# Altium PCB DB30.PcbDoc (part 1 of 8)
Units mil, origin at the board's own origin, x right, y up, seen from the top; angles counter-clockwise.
Board outline 3236.22 x 4456.69 mil, 8 copper layers (Top Layer, MidLayer1, MidLayer2, GND-Layer5, MidLayer3, VCC, MidLayer4, Bottom Layer), stack 61.8 mil thick; 219 components, 472 nets, 1811 pads, 1561 vias.
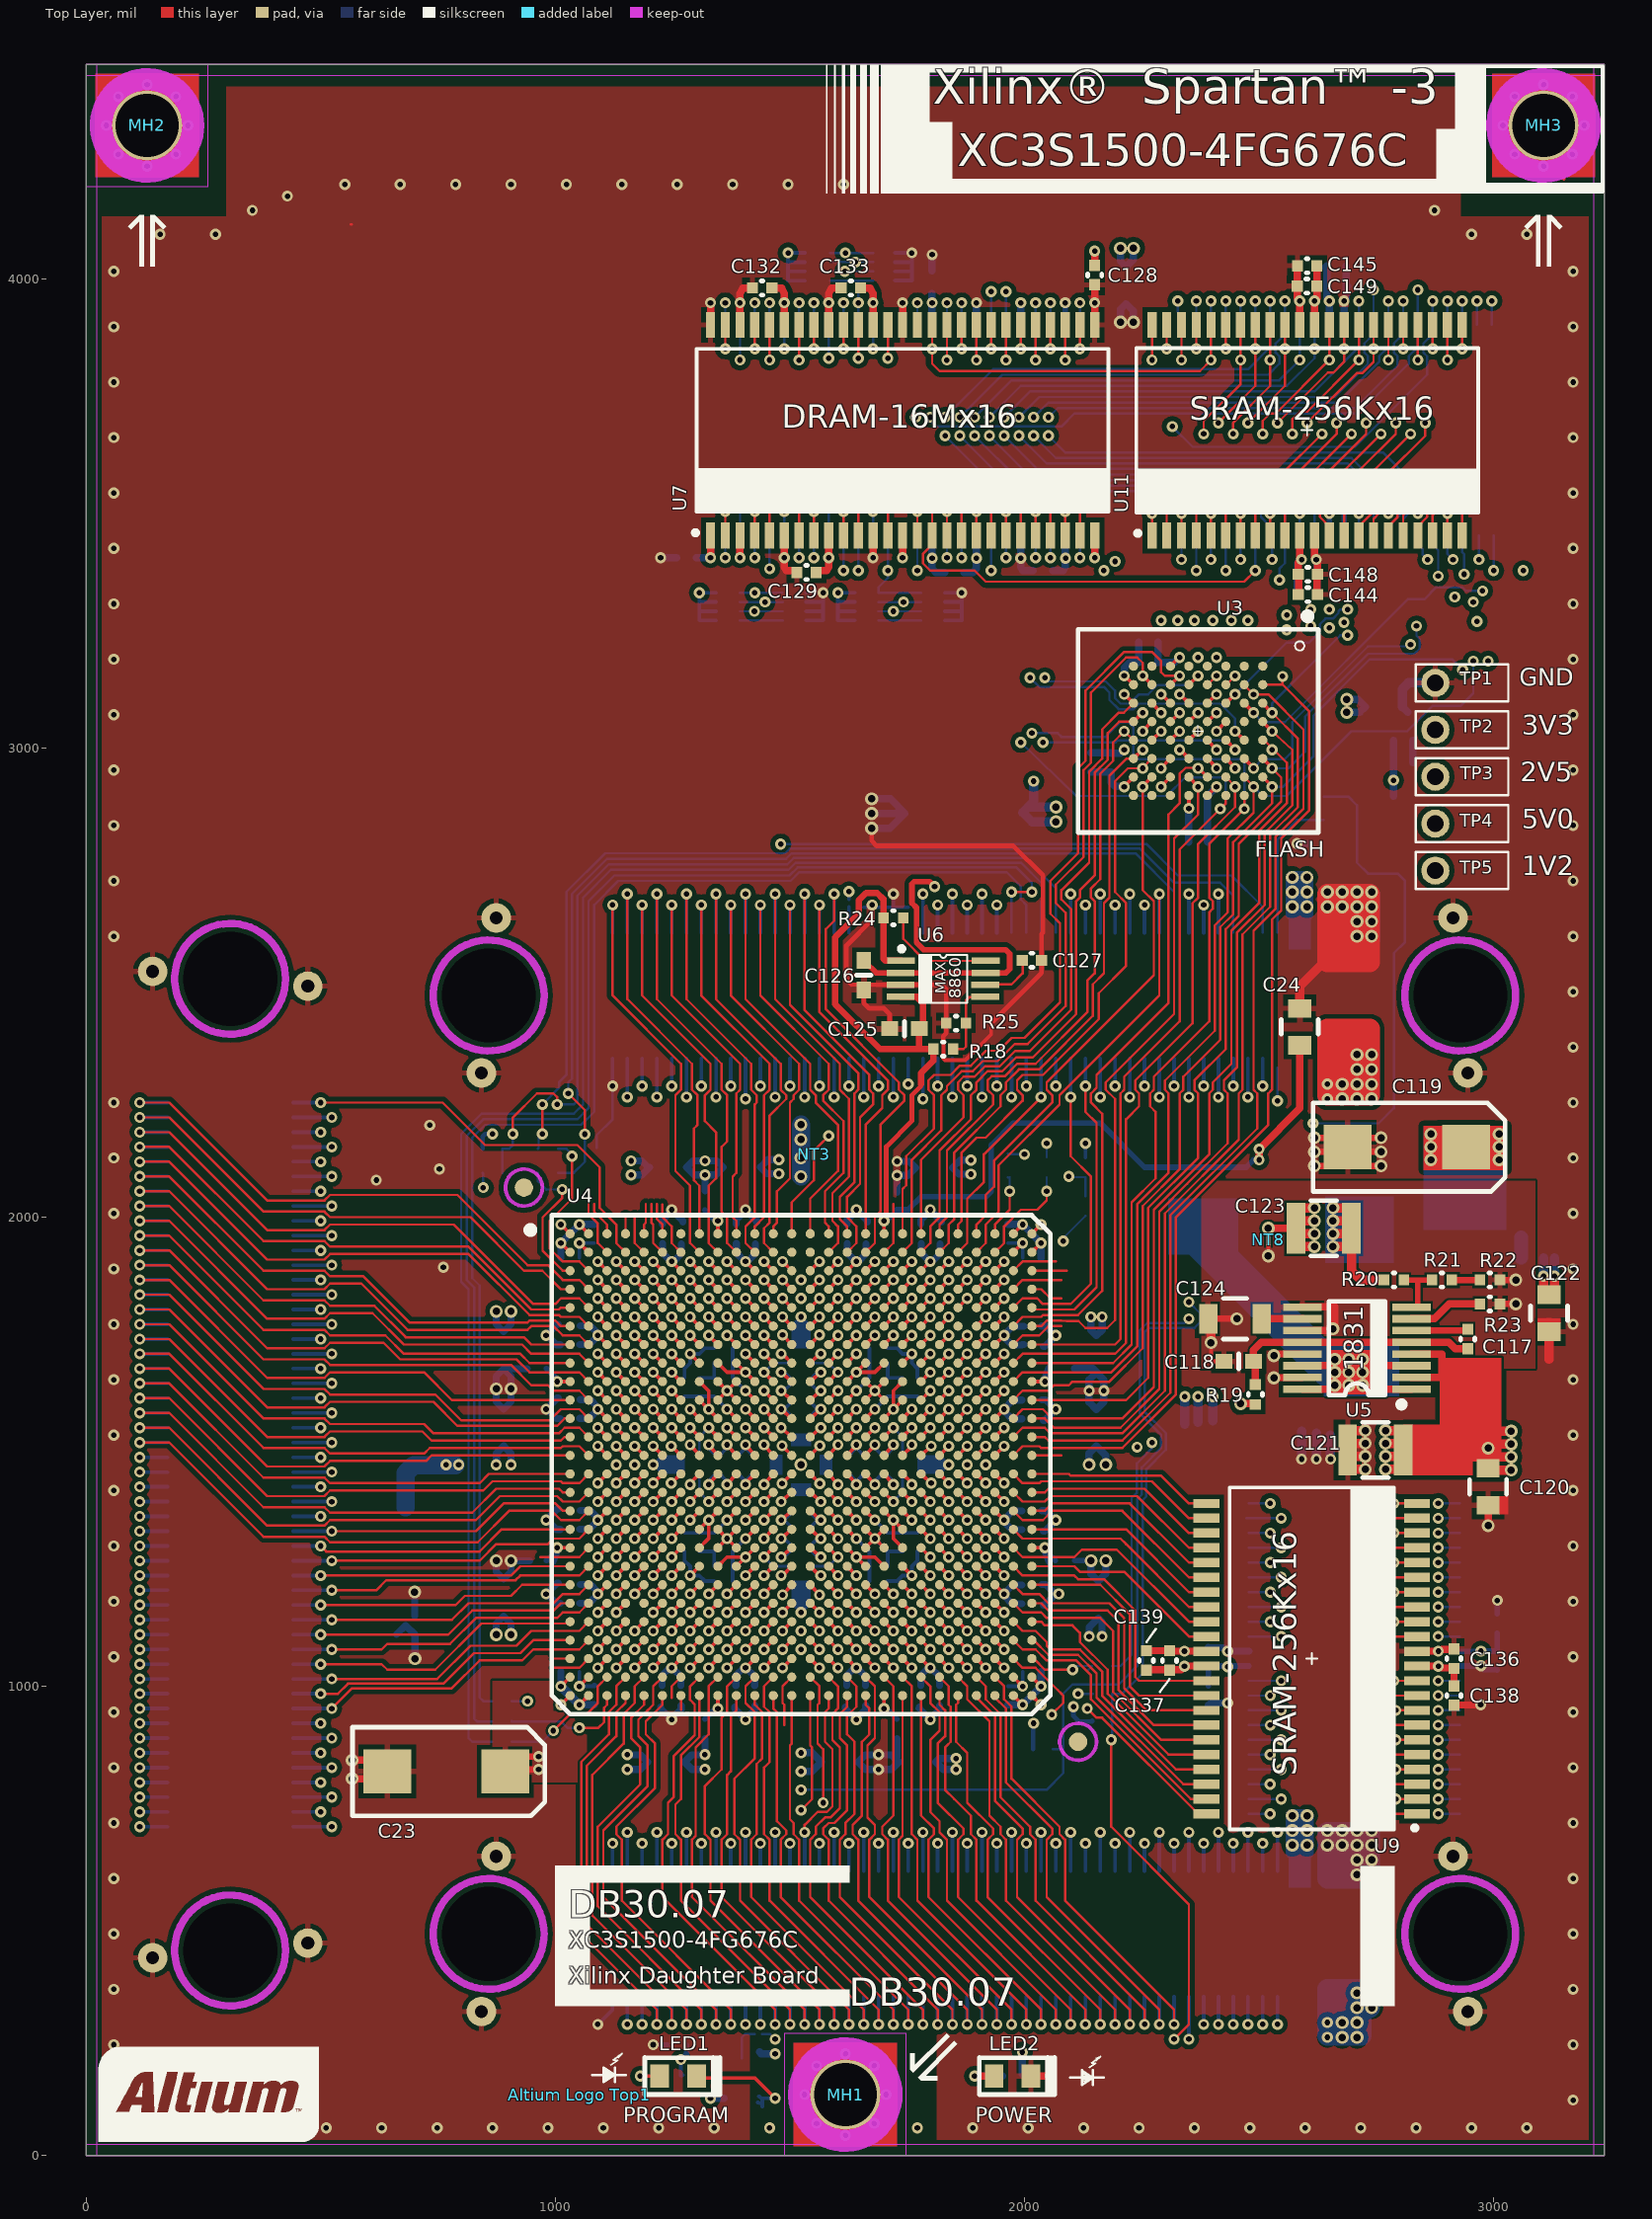
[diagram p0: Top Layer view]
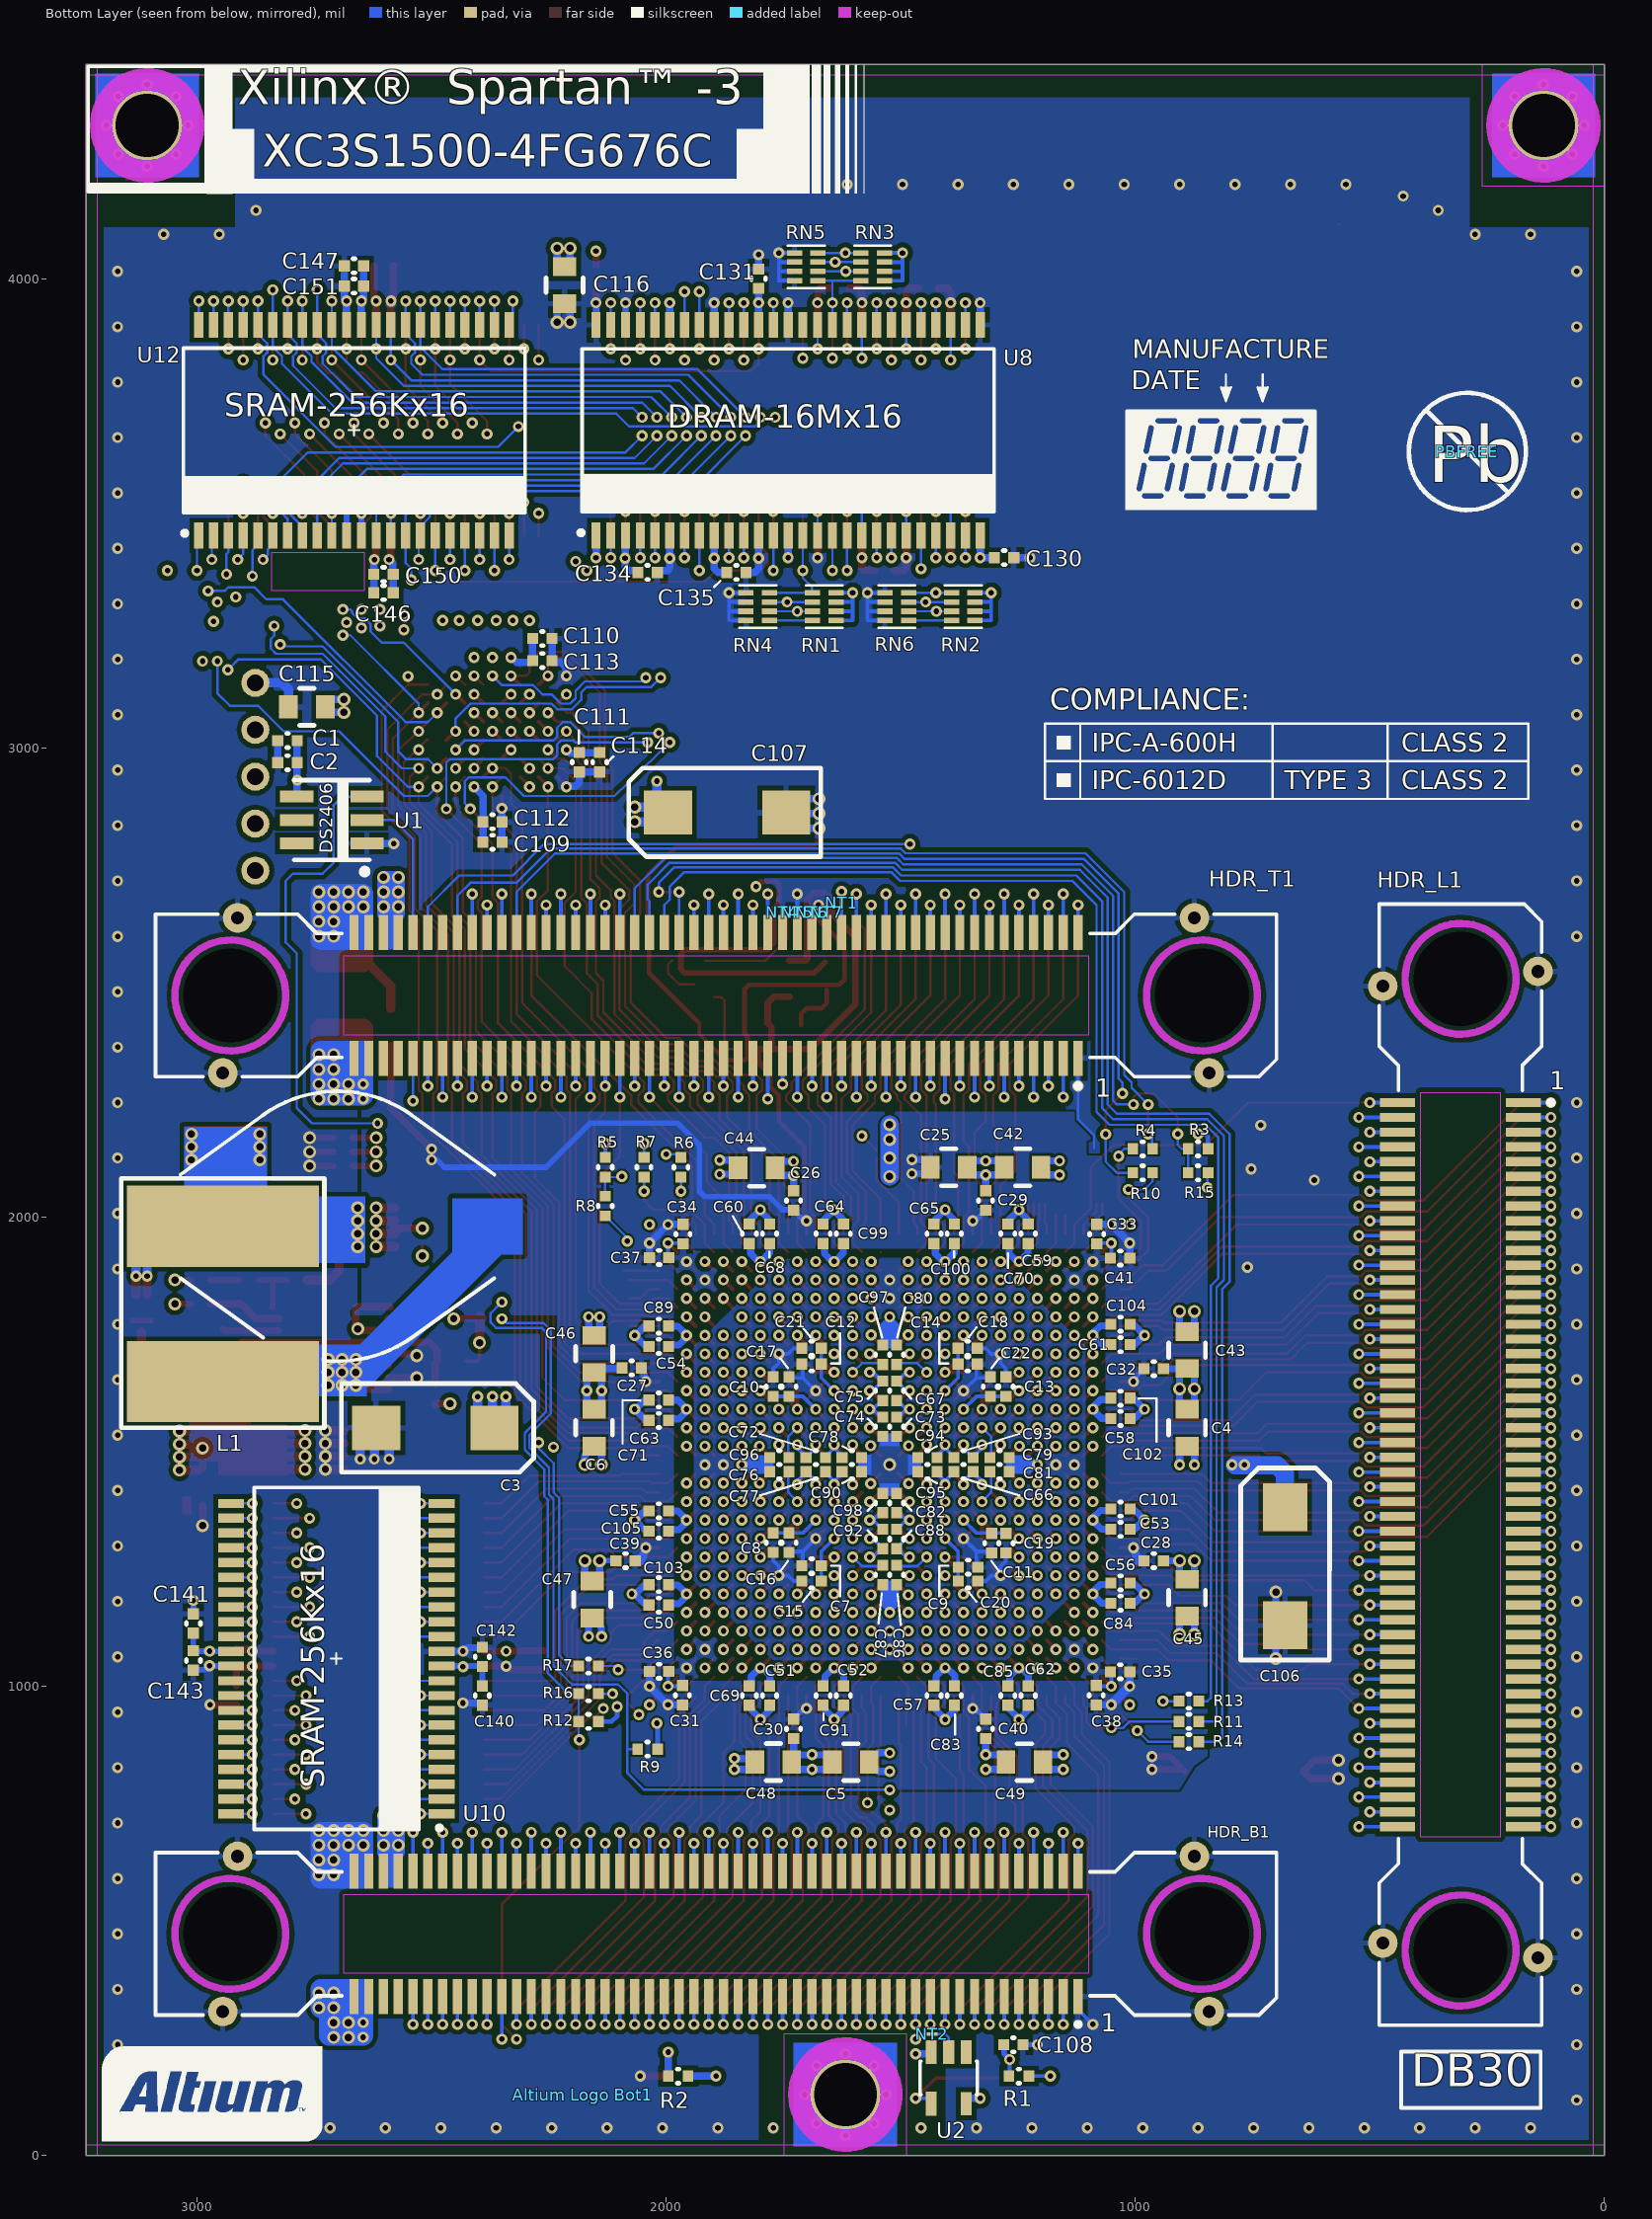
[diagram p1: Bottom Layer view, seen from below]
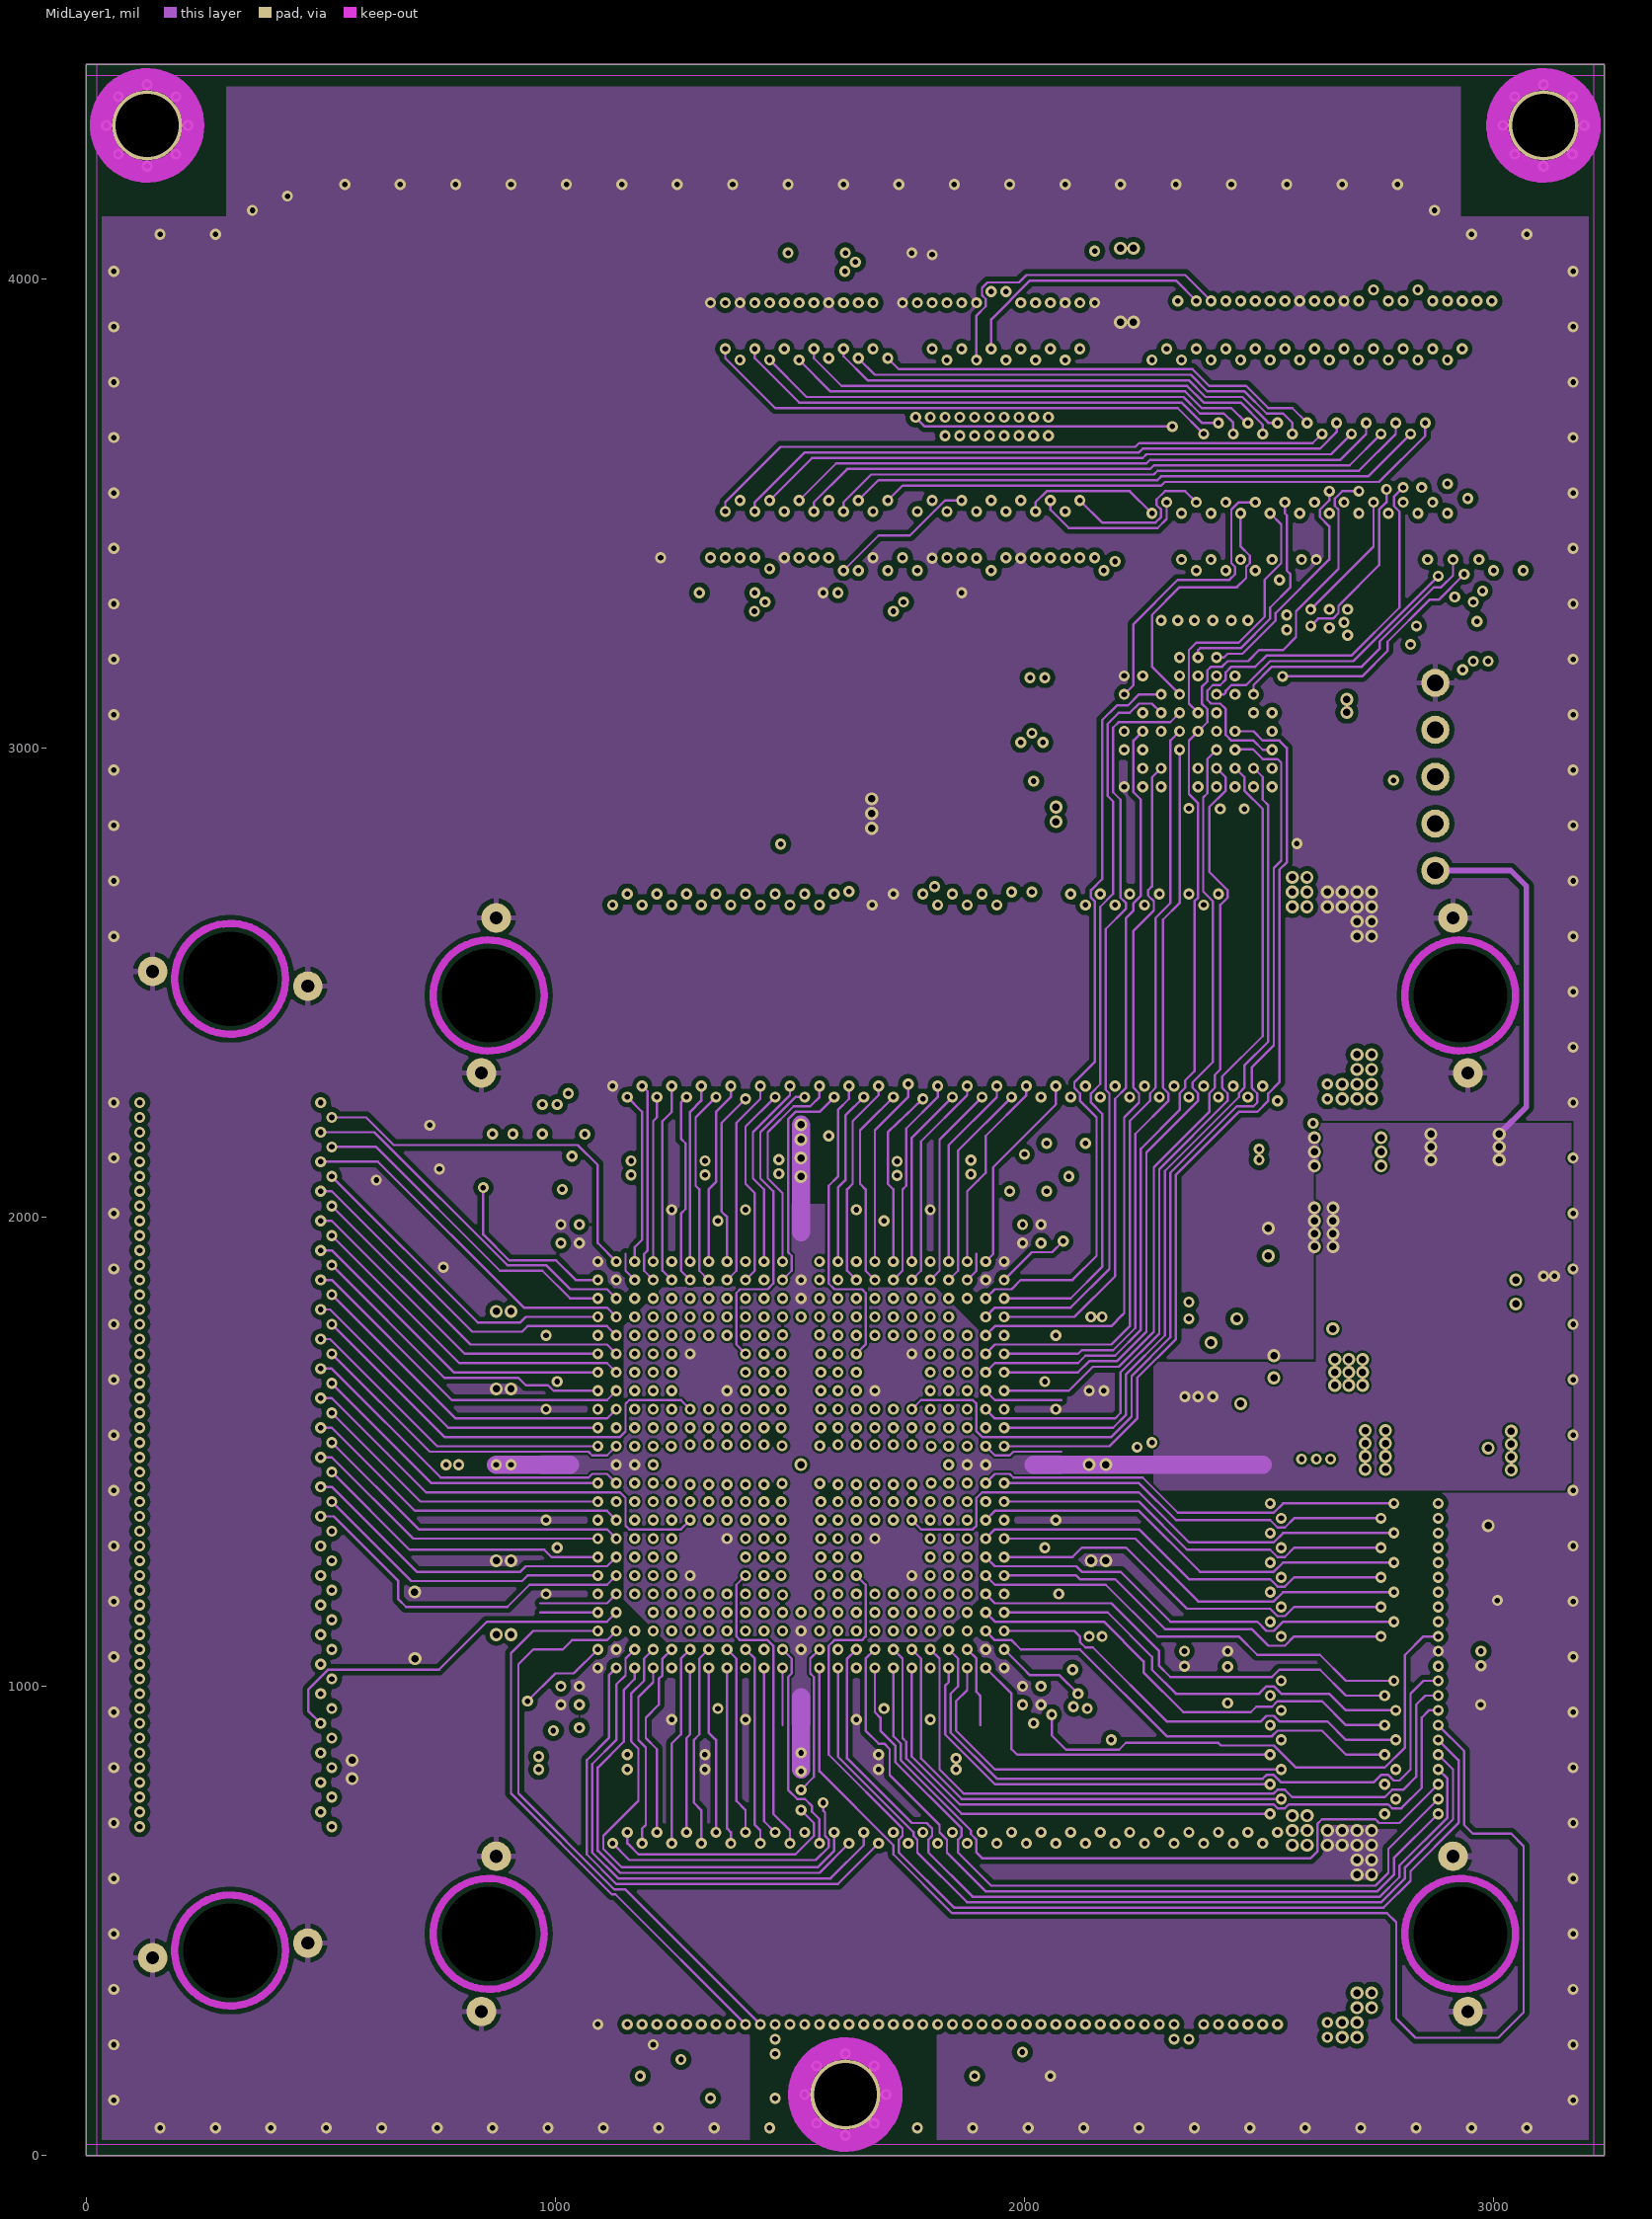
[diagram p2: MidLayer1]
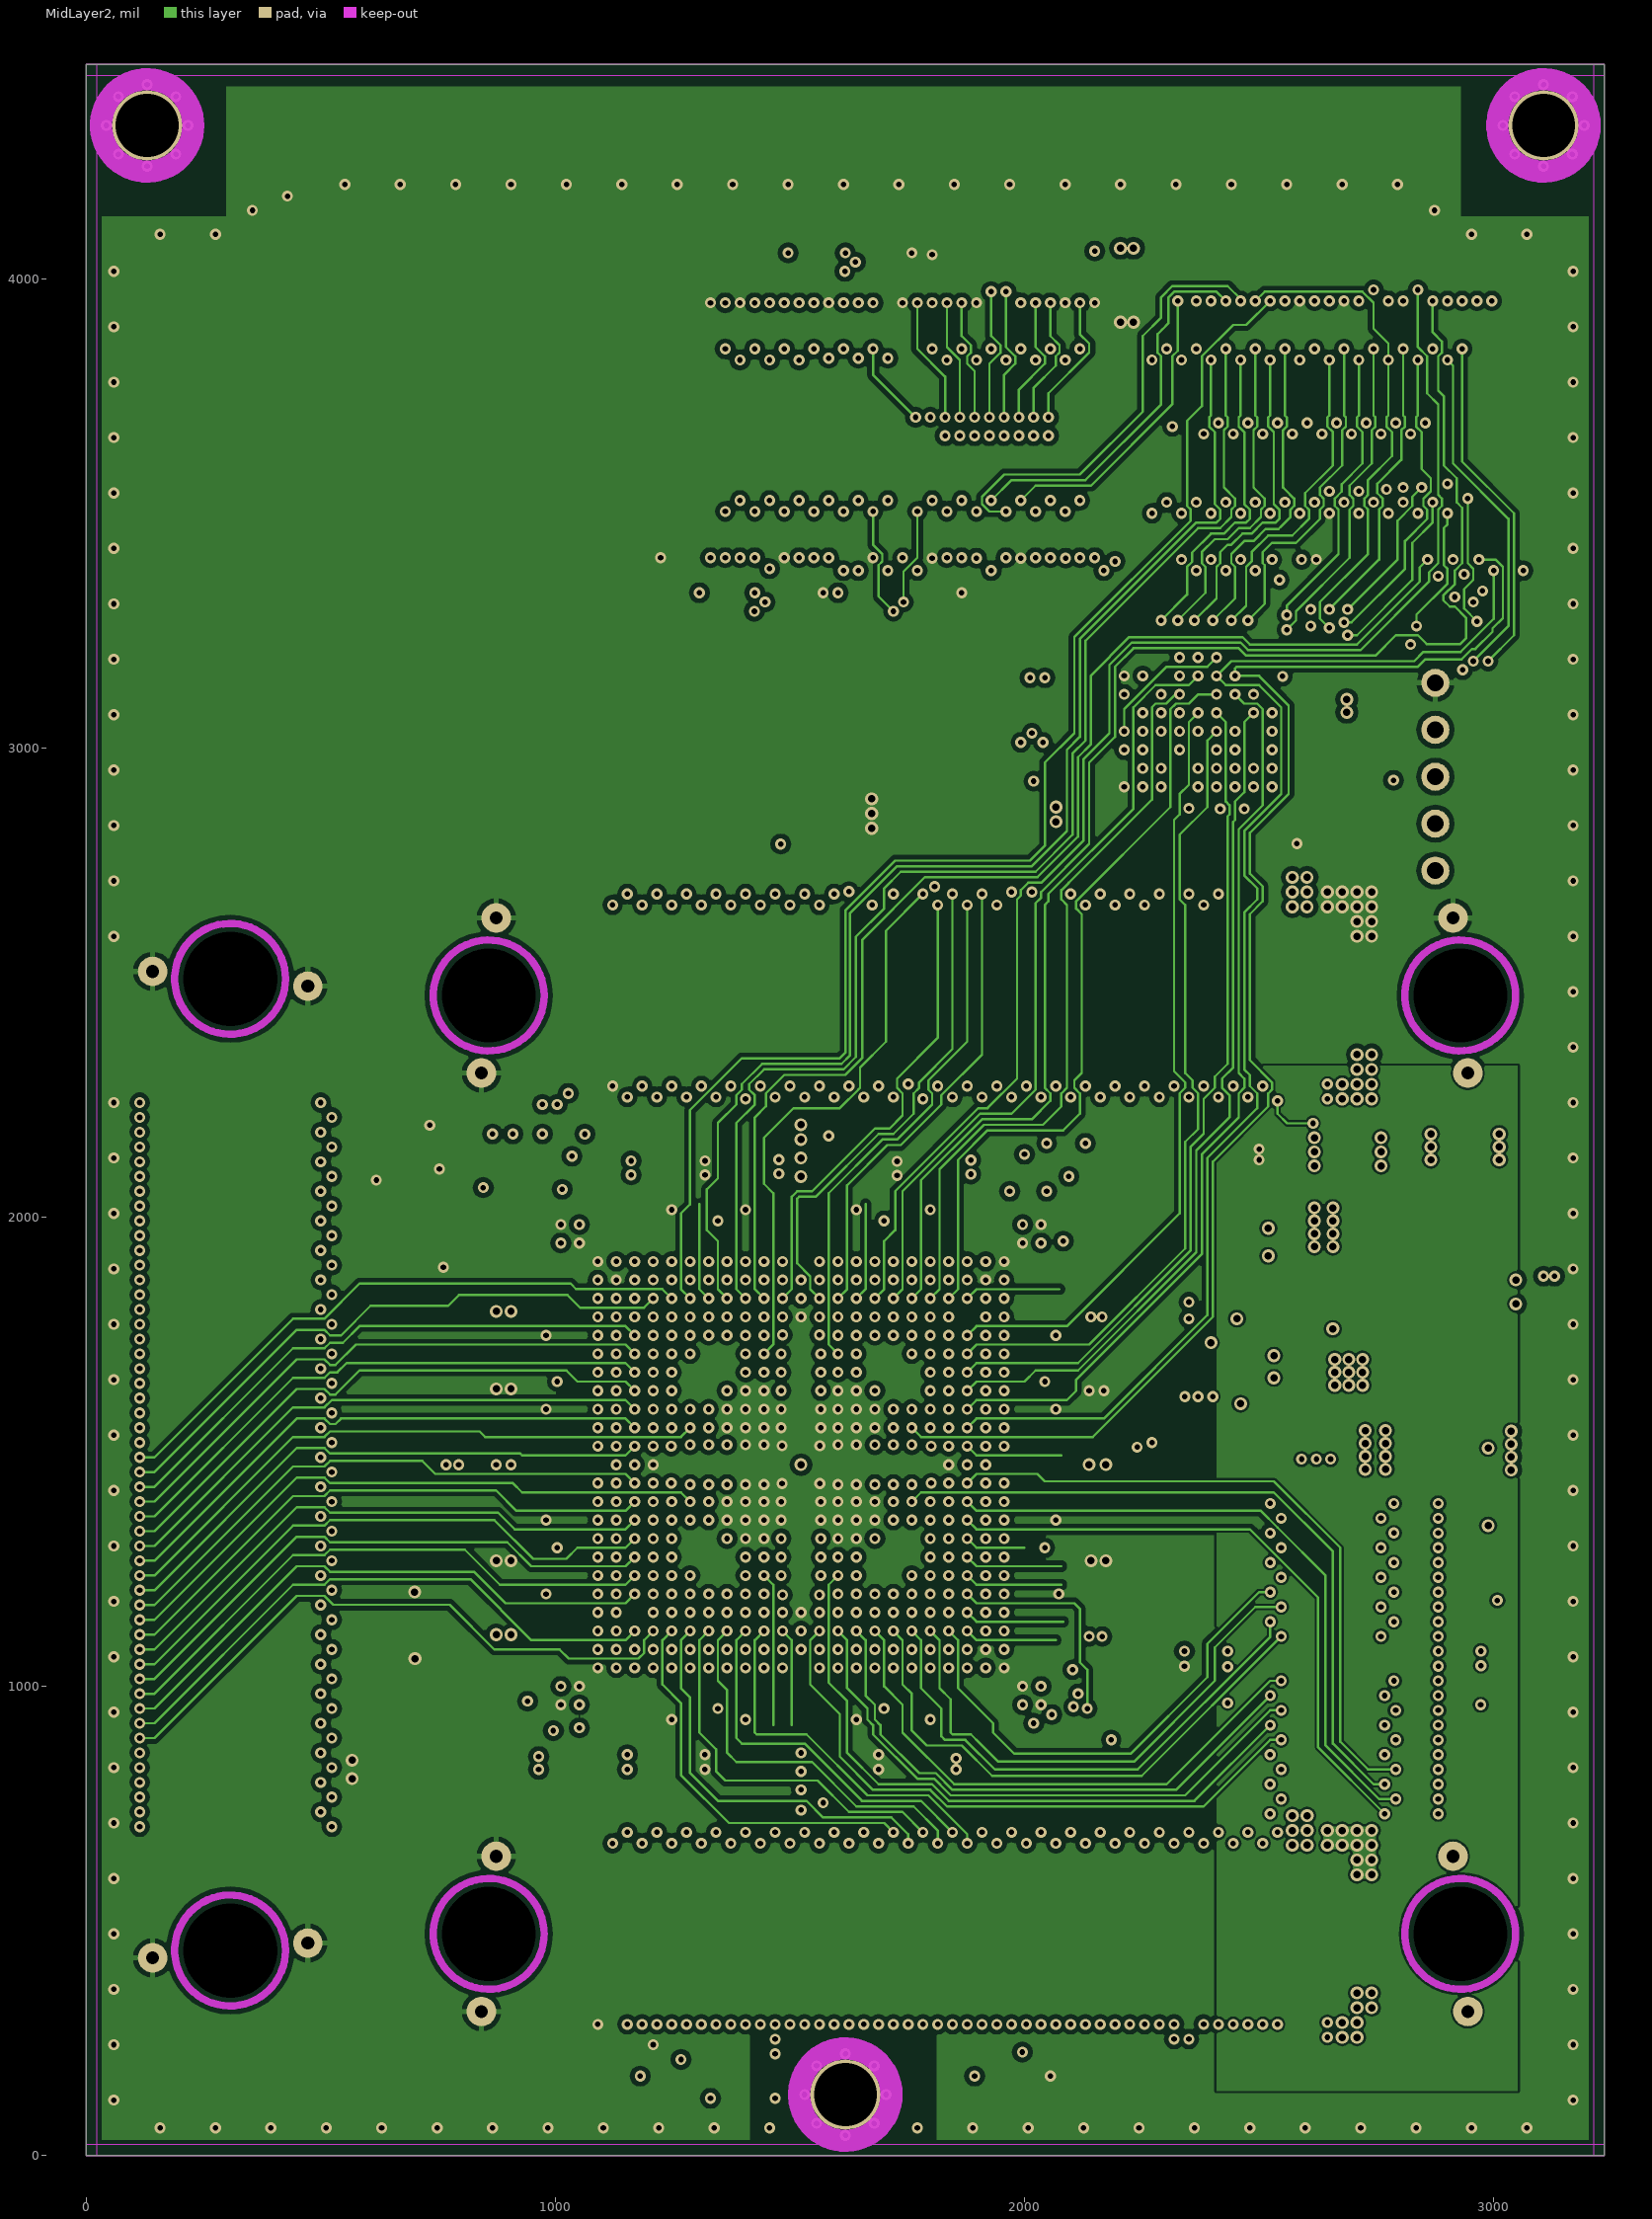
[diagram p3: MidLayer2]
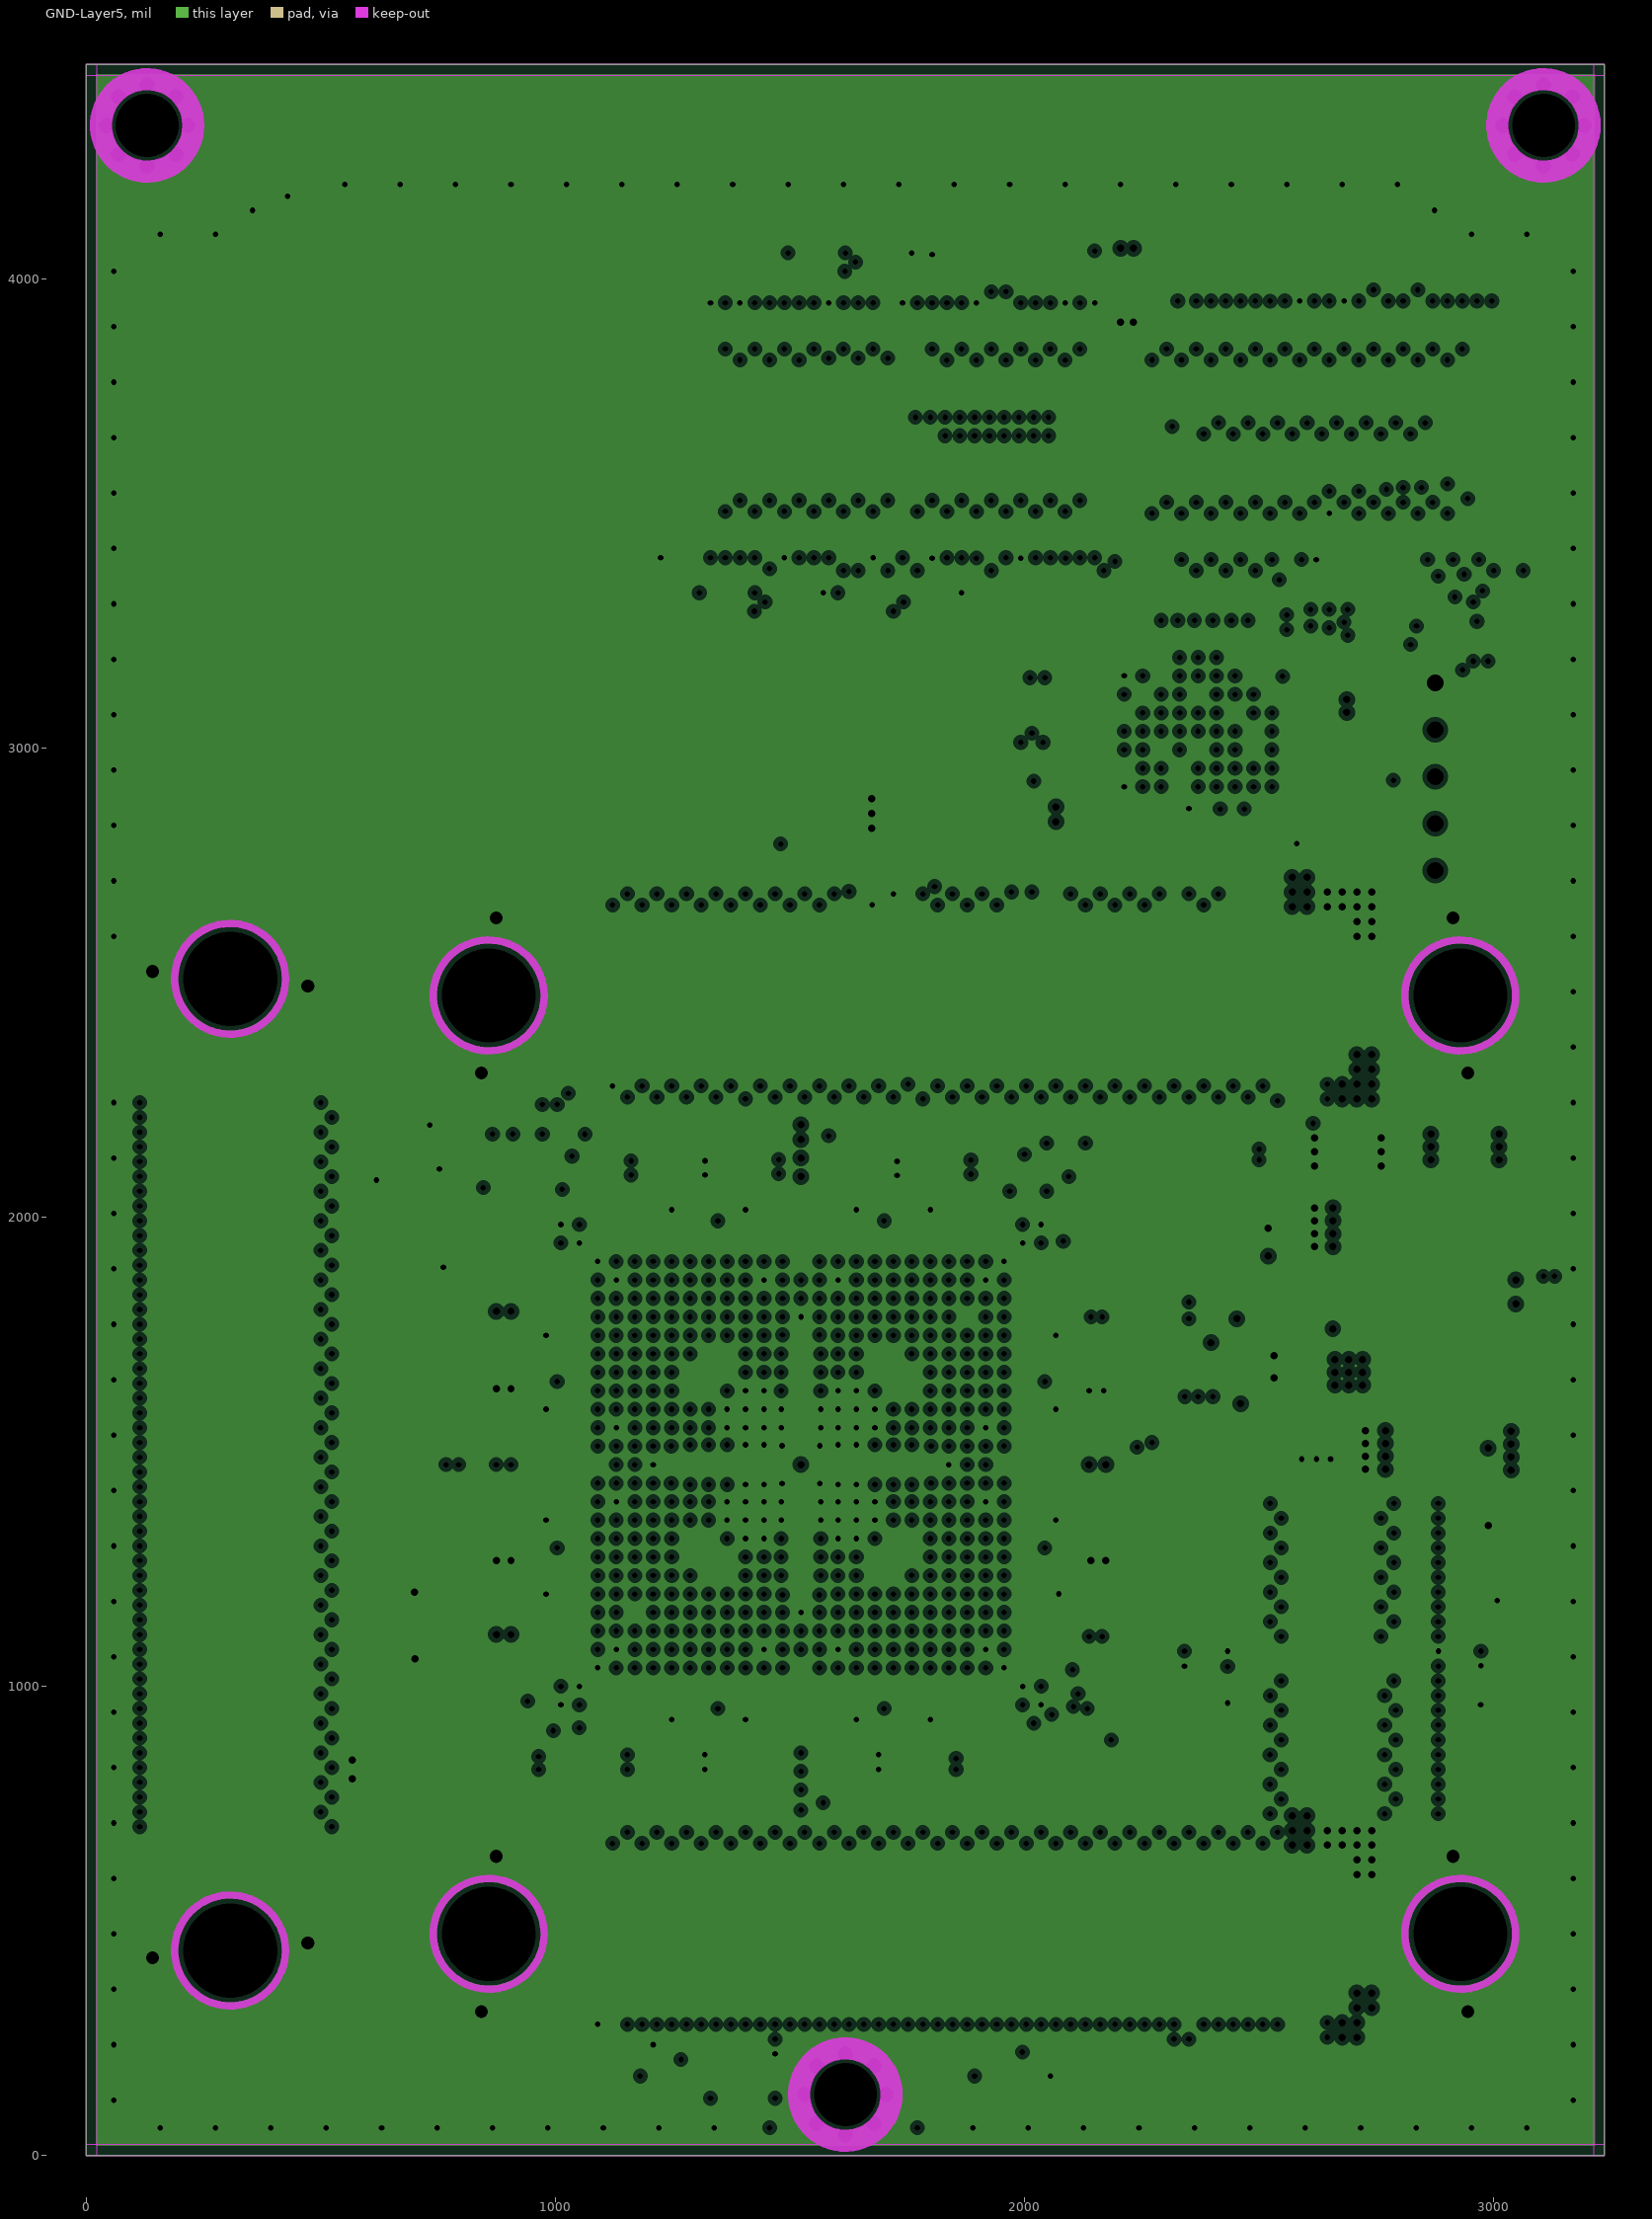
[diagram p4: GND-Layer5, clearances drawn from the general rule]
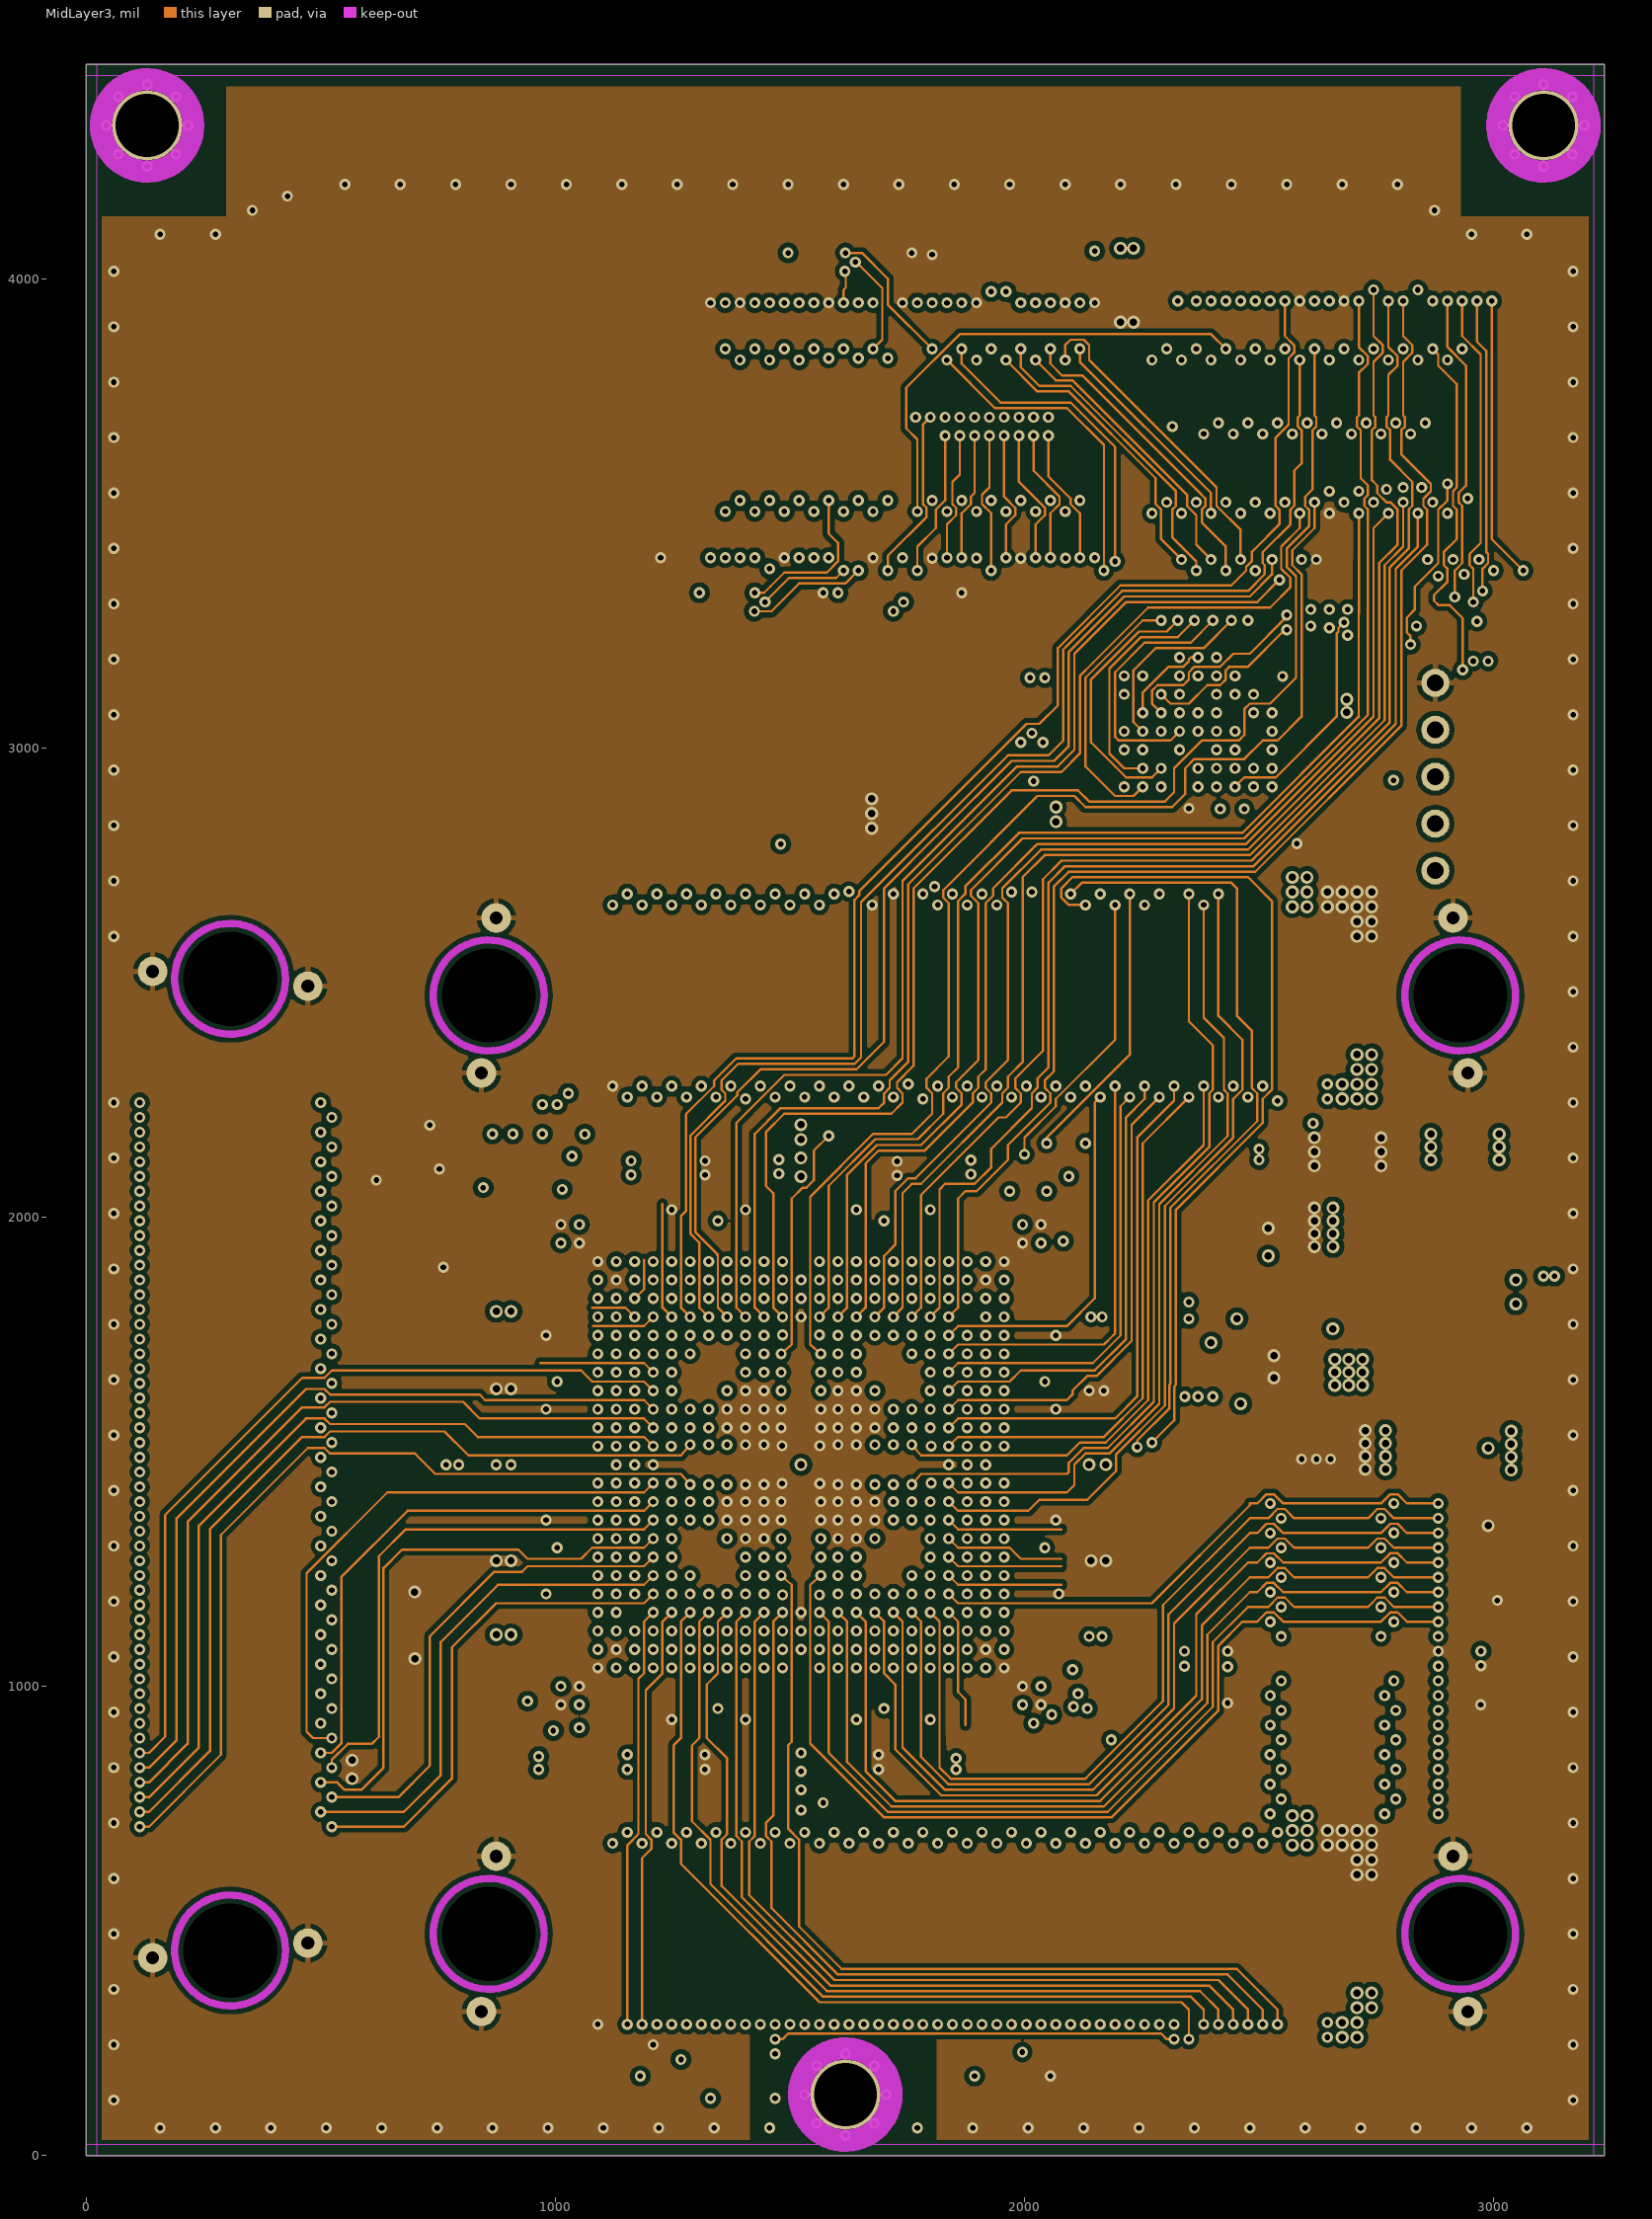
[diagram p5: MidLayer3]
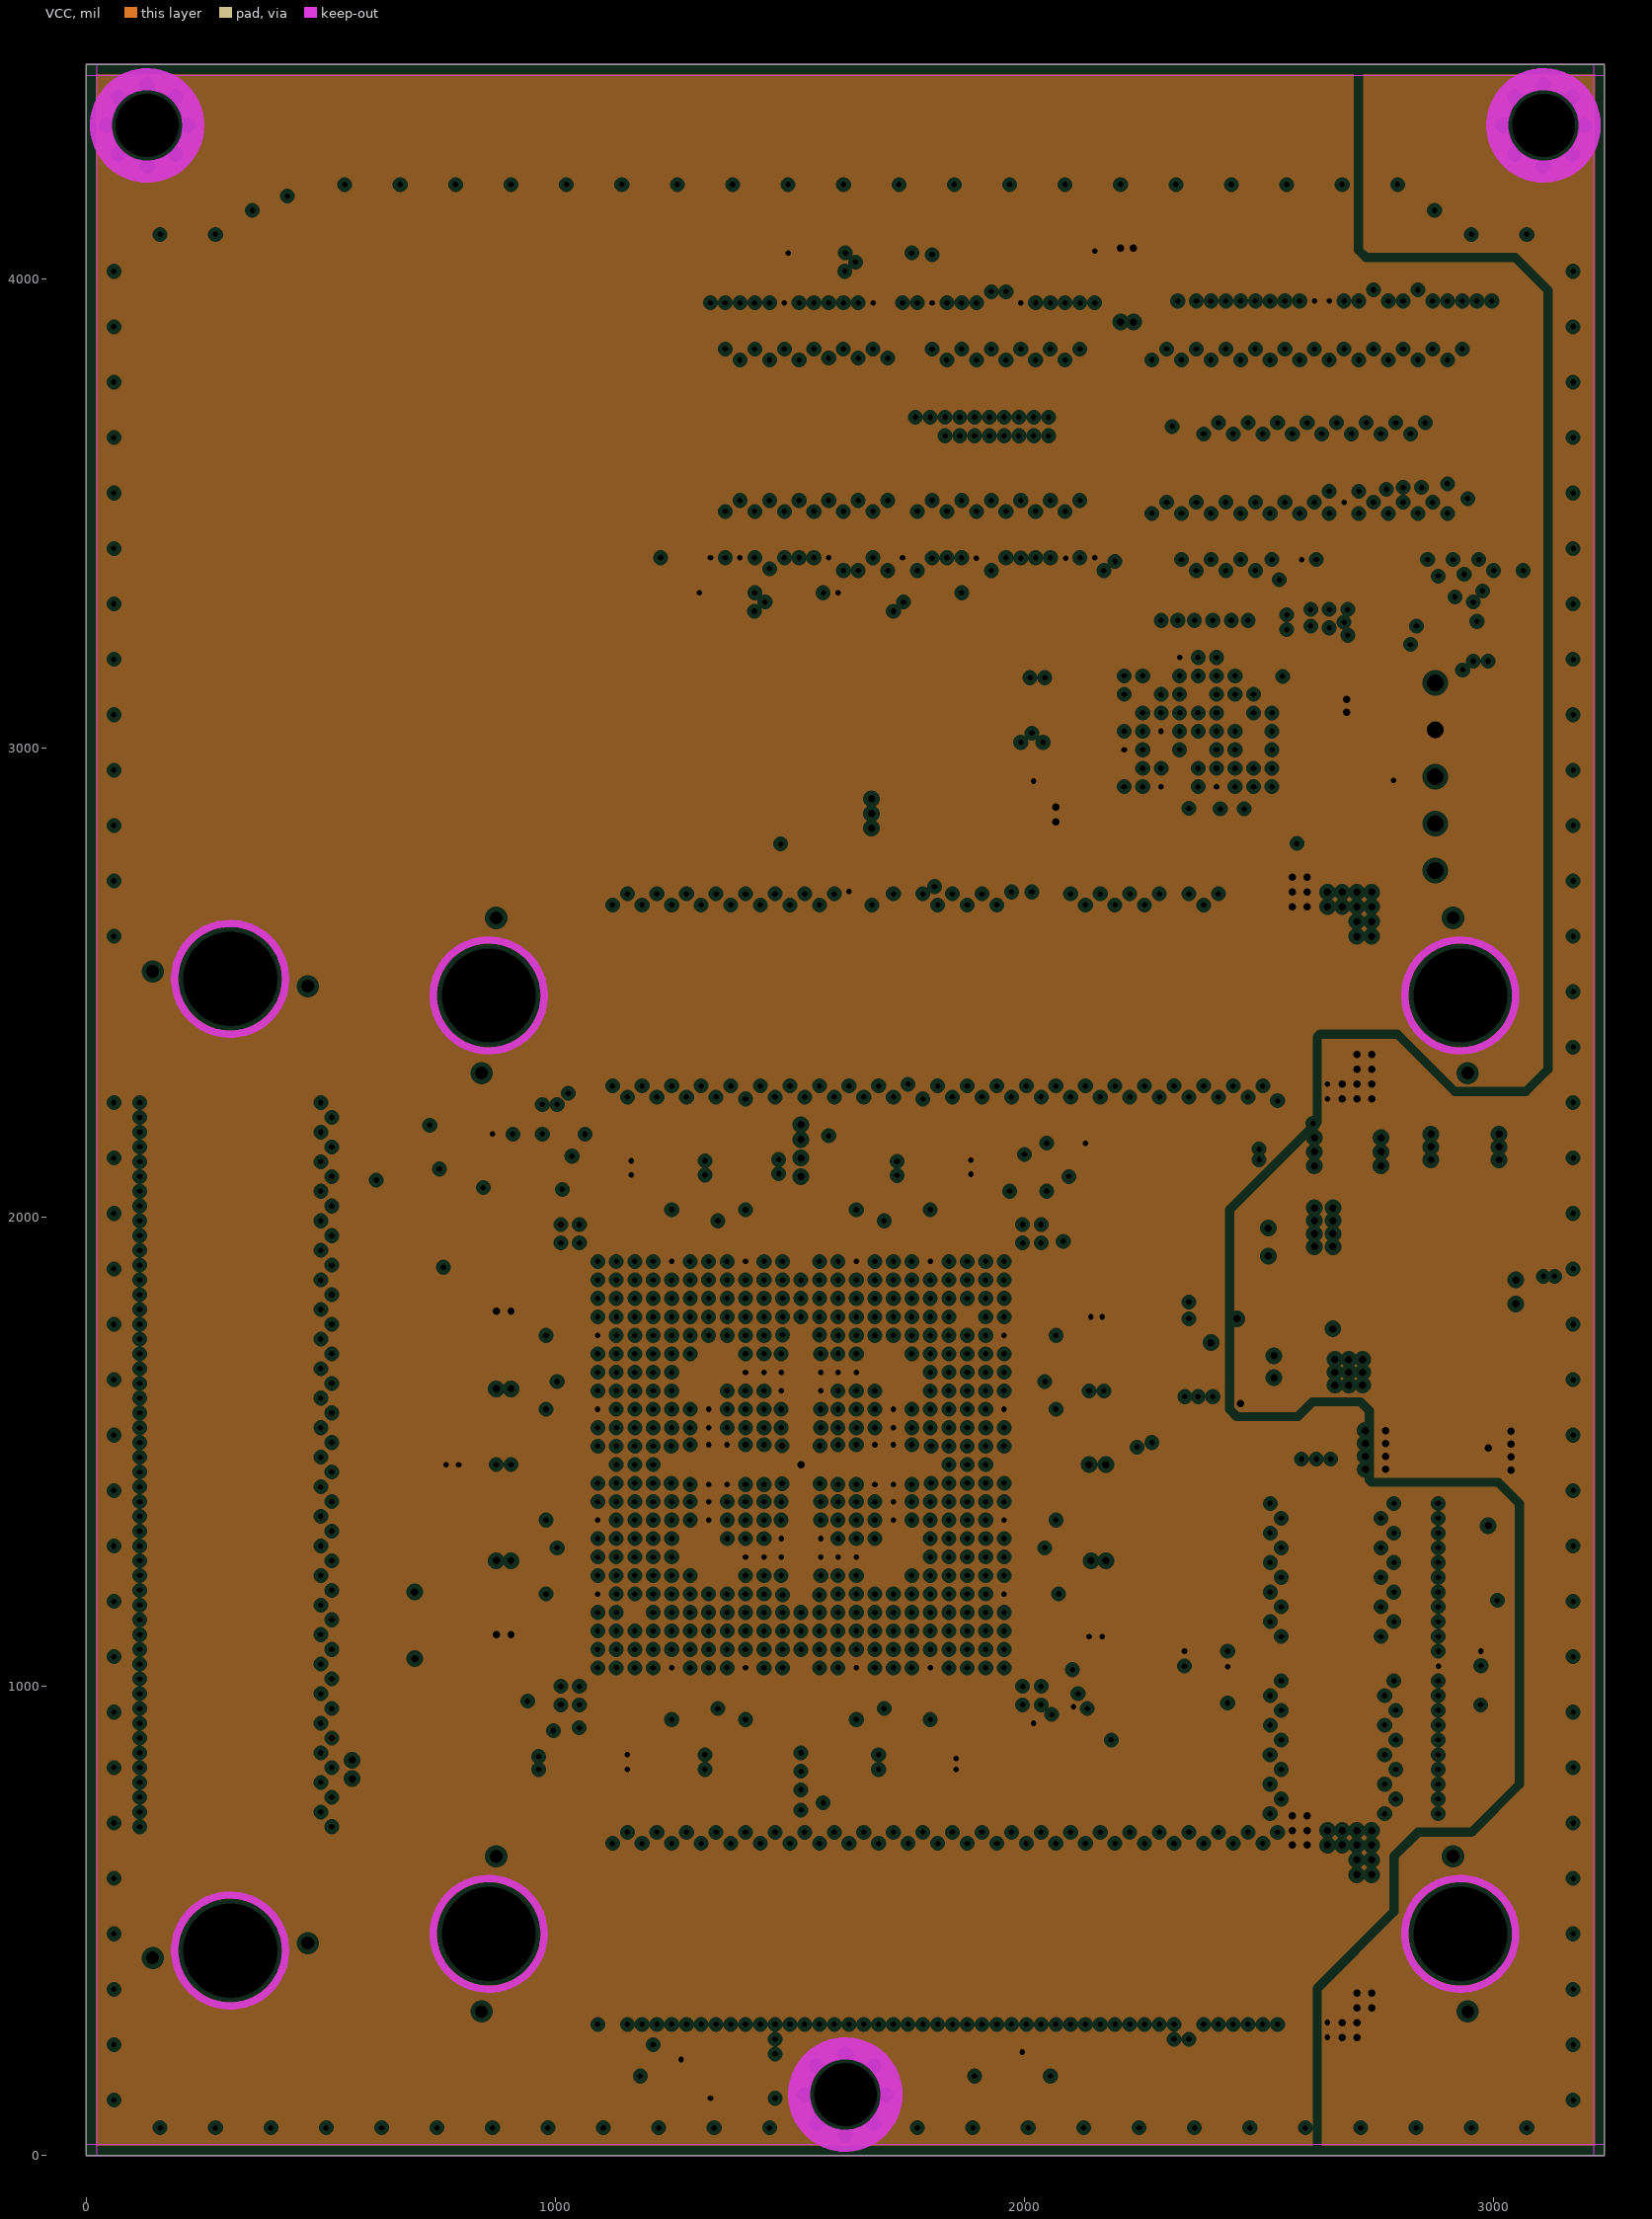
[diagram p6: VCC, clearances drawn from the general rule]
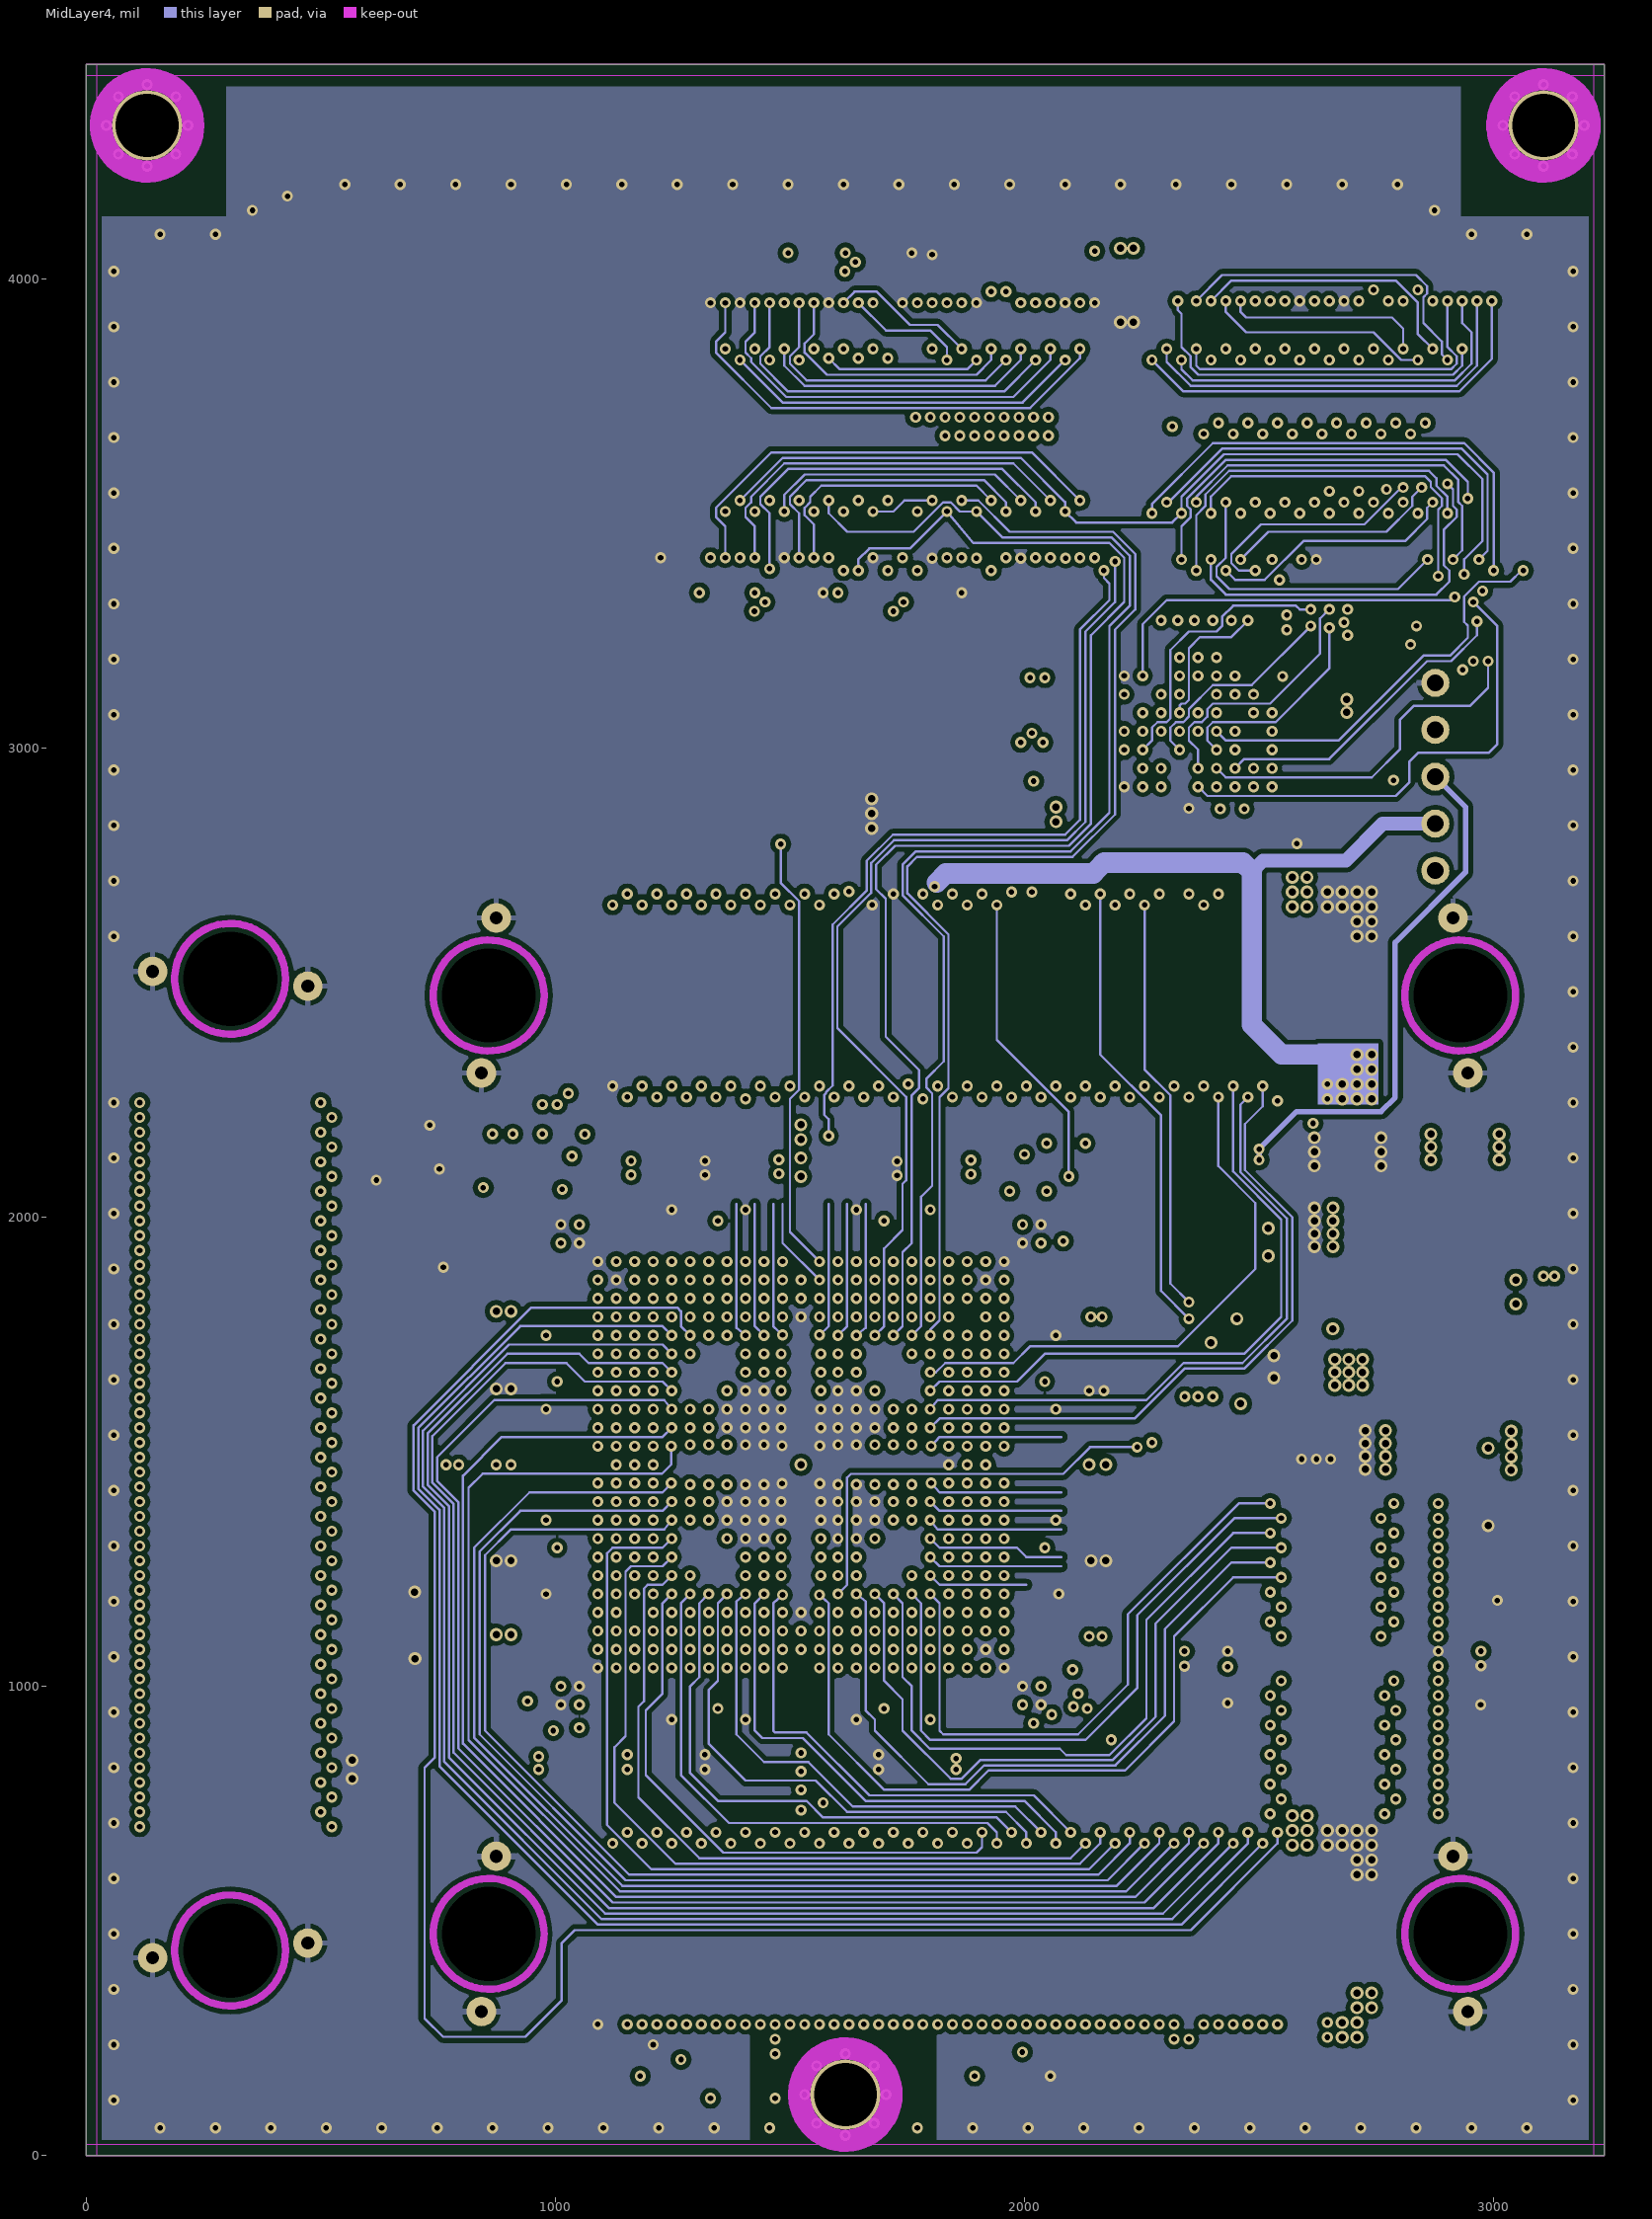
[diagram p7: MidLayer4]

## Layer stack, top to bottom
Top Layer: signal copper 1.7
Dielectric: prepreg 5, FR-4, Dk 4.2
MidLayer1: signal copper 1.4
Dielectric: core 10, FR-4, Dk 4.2
MidLayer2: signal copper 1.4
Dielectric: prepreg 5, FR-4, Dk 4.2
GND-Layer5: plane copper 1.4, net GND
Dielectric: core 10, FR-4, Dk 4.2
MidLayer3: signal copper 1.4
Dielectric: prepreg 5, FR-4, Dk 4.2
VCC: plane copper 1.4, net (Multiple Nets)
Dielectric: core 10, FR-4, Dk 4.2
MidLayer4: signal copper 1.4
Dielectric: prepreg 5, FR-4, Dk 4.2
Bottom Layer: signal copper 1.7

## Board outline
0,0 0,4456.69 1523.62,4456.69 3236.22,4456.69 3236.22,0

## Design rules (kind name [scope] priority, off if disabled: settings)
Clearance Clearance_Poly_Tight [InNamedPolygon('FPGAPWR-BL-1V2') Or InNamedPolygon('FPGAPWR-BL-3V3') Or InNamedPolygon('FPGAPWR-BL-2V5A') Or InNamedPolygon('FPGAPWR-BL-2V5B') Or InNamedPolygon('FPGAPWR-BL-2V5C') Or InNamedPolygon('FPGAPWR-BL-2V5D') Or InNamedPolygon('FPGAPWR-ML1-1V2') Or InNamedPolygon('FPGAPWR-BL-2V5E') Or InNamedPolygon('1V2-CONNECT-TO-L1-C17' ) Or InNamedPolygon('2V5') Or InNamedPolygon('LX') Or InNamedPolygon('2V5-TOP-CAP') Or InNamedPolygon('AGND-TOP')] p1: gap=5
Clearance Clearance_Polygon [InPolygon] p2: gap=10
Clearance "Pad-Pad Clearance" [IsPad vs IsPad] p3: gap=5
Clearance "Via-Pad Clearance" [IsVia vs IsPad] p4: gap=3.94
Clearance "General Clearance" [All] p5: gap=5
ComponentClearance [All] p1 off: gap=7.87 collisioncheckmode=3 verticalgap=10 showdistances=FALSE
DiffPairsRouting [All] p1: maxlimit=5 minlimit=5 mostfreqgap=5 maxuncoupledlength=200
FabricationTestPointUsage TestPointUsage [All] p1 off: valid=0 allowmultiple=FALSE
FabricationTestpoint Testpoint [All] p1 off: side=3 testpointundercomponent=TRUE minsize=40 maxsize=100 preferedsize=60 minholesize=0 maxholesize=40 preferedholesize=32 testpointgrid=1 allowsidetop=TRUE allowsidebottom=TRUE usegrid=TRUE gridtolerance=0.01
HoleSize [All] p1: absolutevalues=TRUE maxlimit=204.72 minlimit=7.87 maxpercent=80.000 minpercent=20.000
HoleToHoleClearance [All] p1: gap=4 allowstackedmicrovias=TRUE
MatchedLengths DiffPair_MatchedLengths [(IsDifferentialPair And (Name = 'DIFF_RX1'))] p1: tolerance=1000 checknetsindiffpair=TRUE checkdiffpairvsdiffpair=TRUE checkothers=TRUE
MinimumAnnularRing MinimumAnnularRing_NonPlated [(ObjectKind = 'Pad') And (HoleDiameter >= '0.7') And (PadIsPlated = 'False')] p1: minimumring=-196.85
MinimumAnnularRing [All] p2: minimumring=5.91
MinimumSolderMaskSliver [All] p1: minsoldermaskwidth=2
PlaneClearance [All] p1: clearance=10
PlaneConnect [All] p1: planeconnectstyle=Direct reliefexpansion=19.68 reliefentries=4 reliefconductorwidth=9.84 reliefairgap=9.84
PolygonConnect PolygonConnect_Via [IsVia] p1: connectstyle=Direct reliefconductorwidth=10 reliefentries=4 polygonreliefangle="90 Angle"
PolygonConnect "PolygonConnect - Heatsink" [(HasFootprint('TO-263') AND InNet('VCCINT'))] p2: connectstyle=Direct reliefconductorwidth=10 reliefentries=4 polygonreliefangle="90 Angle"
PolygonConnect [All] p3: connectstyle=Relief reliefconductorwidth=11.81 reliefentries=4 polygonreliefangle="90 Angle"
RoutingVias [All] p1: holewidth=11.81 width=23.62 viastyle="Through Hole" minholewidth=11.81 minwidth=23.62 maxholewidth=19.68 maxwidth=35.43
ShortCircuit ShortCircuit_1 [Net = 'No Net' vs Net = 'No Net'] p1: allowed=TRUE
ShortCircuit [All] p2: allowed=FALSE
SilkToSilkClearance SilkToSilkClearance_InvToFill [(ObjectKind = 'Text') And (TextKind <> 'Stroke Font') vs IsFill] p1: silktosilkclearance=0
SilkToSilkClearance SilkToSilkClearance_Labels [(ObjectKind = 'Text') And (TextKind <> 'Stroke Font') vs (ObjectKind = 'Text') And (TextKind <> 'Stroke Font')] p2: silktosilkclearance=0
SilkToSilkClearance SilkToSilkClearance_Pb [(ObjectKind = 'Text') And (StringText = 'Pb') vs istrack and onsilkscreen] p3: silktosilkclearance=0
SilkToSilkClearance [All] p4: silktosilkclearance=2
SilkscreenOverComponentPads [All] p1: minsilkscreentomaskgap=2
SolderMaskExpansion SolderMaskExpansion_Vias [IsVia] p1: expansion=-25.59
SolderMaskExpansion [All] p2: expansion=1.5
Width [All] p1: maxlimit=98.43 minlimit=5 preferedwidth=5
16 further rules are at their usual default settings.

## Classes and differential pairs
channel class SRAM_256Kx16_TSOP44: U_SRAM_K6R4016V1D-TC10T_256Kx161 U_SRAM_K6R4016V1D-TC10T_256Kx162
component class U_Bypass_Board: C106 C107
component class U_PSU_MAX8860_ADJ: C125 C126 C127 R24 R25 U6
component class COM_SRAM: C144 C145 C146 C147 C148 C149 C150 C151 U11 U12
component class COM_SDRAM: C128 C129 C130 C131 C132 C133 C134 C135 U7 U8
component class U_PSU_MAX1831_1V2_ALT: C117 C118 C119 C120 C121 C122 C123 C124 L1 R19 R20 R21 R22 R23 TP7 TP8 U5
component class U_SRAM_K6R4016V1D-TC10T_256Kx162: C1_SM C2_SM C4_SM C140 C141 C142 C143 U1_SM U10
component class U_SRAM_K6R4016V1D-TC10T_256Kx161: C136 C137 C138 C139 U9
component class U_DaughterBoard_LEDS: C108 LED1 LED2 R1 R2 U2
component class COM_FLASH: C109 C110 C111 C112 C113 C114 U3
component class U_CommonMemory_Termination: RN1 RN2 RN3 RN4 RN5 RN6 RN7 RN8 RN9 RN10 RN11 RN12 RN13 RN14 RN15 RN16 RN17 RN18 RN19 RN20 RN21 RN22 RN23 RN24 RN25 RN26 RN27 RN28 RN29 RN30 RN31 RN32 RN35 RN36
component class U_1WB_DS2406_EPROM: C1 C2 U1
net class SRAM2_D[15..0]: SRAM2_D0 SRAM2_D1 SRAM2_D2 SRAM2_D3 SRAM2_D4 SRAM2_D5 SRAM2_D6 SRAM2_D7 SRAM2_D8 SRAM2_D9 SRAM2_D10 SRAM2_D11 SRAM2_D12 SRAM2_D13 SRAM2_D14 SRAM2_D15
net class SRAM2_A[18..0]: SRAM2_A0 SRAM2_A1 SRAM2_A2 SRAM2_A3 SRAM2_A4 SRAM2_A5 SRAM2_A6 SRAM2_A7 SRAM2_A8 SRAM2_A9 SRAM2_A10 SRAM2_A11 SRAM2_A12 SRAM2_A13 SRAM2_A14 SRAM2_A15 SRAM2_A16 SRAM2_A17 SRAM2_A18
net class SRAM1_D[15..0]: SRAM1_D0 SRAM1_D1 SRAM1_D2 SRAM1_D3 SRAM1_D4 SRAM1_D5 SRAM1_D6 SRAM1_D7 SRAM1_D8 SRAM1_D9 SRAM1_D10 SRAM1_D11 SRAM1_D12 SRAM1_D13 SRAM1_D14 SRAM1_D15
net class SRAM1_A[18..0]: SRAM1_A0 SRAM1_A1 SRAM1_A2 SRAM1_A3 SRAM1_A4 SRAM1_A5 SRAM1_A6 SRAM1_A7 SRAM1_A8 SRAM1_A9 SRAM1_A10 SRAM1_A11 SRAM1_A12 SRAM1_A13 SRAM1_A14 SRAM1_A15 SRAM1_A16 SRAM1_A17 SRAM1_A18
component class U_PSU: C115 C116 NT8 R18 TP1 TP2 TP3 TP4 TP5
net class EXTEND_C[49..0]: EXTEND_C0 EXTEND_C1 EXTEND_C2 EXTEND_C3 EXTEND_C4 EXTEND_C5 EXTEND_C6 EXTEND_C7 EXTEND_C8 EXTEND_C9 EXTEND_C10 EXTEND_C11 EXTEND_C12 EXTEND_C13 EXTEND_C14 EXTEND_C15 EXTEND_C16 EXTEND_C17 EXTEND_C18 EXTEND_C19 EXTEND_C20 EXTEND_C21 EXTEND_C22 EXTEND_C23 EXTEND_C24 EXTEND_C25 EXTEND_C26 EXTEND_C27 EXTEND_C28 EXTEND_C29 EXTEND_C30 EXTEND_C31 EXTEND_C32 EXTEND_C33 EXTEND_C34 EXTEND_C35 EXTEND_C36 EXTEND_C37 EXTEND_C38 EXTEND_C39 EXTEND_C40 EXTEND_C41 EXTEND_C42 EXTEND_C43 EXTEND_C44 EXTEND_C45 EXTEND_C46 EXTEND_C47 EXTEND_C48 EXTEND_C49
net class EXTEND_B[49..0]: EXTEND_B0 EXTEND_B1 EXTEND_B2 EXTEND_B3 EXTEND_B4 EXTEND_B5 EXTEND_B6 EXTEND_B7 EXTEND_B8 EXTEND_B9 EXTEND_B10 EXTEND_B11 EXTEND_B12 EXTEND_B13 EXTEND_B14 EXTEND_B15 EXTEND_B16 EXTEND_B17 EXTEND_B18 EXTEND_B19 EXTEND_B20 EXTEND_B21 EXTEND_B22 EXTEND_B23 EXTEND_B24 EXTEND_B25 EXTEND_B26 EXTEND_B27 EXTEND_B28 EXTEND_B29 EXTEND_B30 EXTEND_B31 EXTEND_B32 EXTEND_B33 EXTEND_B34 EXTEND_B35 EXTEND_B36 EXTEND_B37 EXTEND_B38 EXTEND_B39 EXTEND_B40 EXTEND_B41 EXTEND_B42 EXTEND_B43 EXTEND_B44 EXTEND_B45 EXTEND_B46 EXTEND_B47 EXTEND_B48 EXTEND_B49
net class EXTEND_A[49..0]: EXTEND_A0 EXTEND_A1 EXTEND_A2 EXTEND_A3 EXTEND_A4 EXTEND_A5 EXTEND_A6 EXTEND_A7 EXTEND_A8 EXTEND_A9 EXTEND_A10 EXTEND_A11 EXTEND_A12 EXTEND_A13 EXTEND_A14 EXTEND_A15 EXTEND_A16 EXTEND_A17 EXTEND_A18 EXTEND_A19 EXTEND_A20 EXTEND_A21 EXTEND_A22 EXTEND_A23 EXTEND_A24 EXTEND_A25 EXTEND_A26 EXTEND_A27 EXTEND_A28 EXTEND_A29 EXTEND_A30 EXTEND_A31 EXTEND_A32 EXTEND_A33 EXTEND_A34 EXTEND_A35 EXTEND_A36 EXTEND_A37 EXTEND_A38 EXTEND_A39 EXTEND_A40 EXTEND_A41 EXTEND_A42 EXTEND_A43 EXTEND_A44 EXTEND_A45 EXTEND_A46 EXTEND_A47 EXTEND_A48 EXTEND_A49
net class DAU_TFT_RED[4..0]: DAU_TFT_RED0 DAU_TFT_RED1 DAU_TFT_RED2 DAU_TFT_RED3 DAU_TFT_RED4
net class DAU_TFT_GREEN[5..0]: DAU_TFT_GREEN0 DAU_TFT_GREEN1 DAU_TFT_GREEN2 DAU_TFT_GREEN3 DAU_TFT_GREEN4 DAU_TFT_GREEN5
net class DAU_TFT_CL[3..1]: DAU_TFT_CL1 DAU_TFT_CL2 DAU_TFT_CL3
net class DAU_TFT_BLUE[4..0]: DAU_TFT_BLUE0 DAU_TFT_BLUE1 DAU_TFT_BLUE2 DAU_TFT_BLUE3 DAU_TFT_BLUE4
net class BUS_A[24..1]: BUS_A1 BUS_A2 BUS_A3 BUS_A4 BUS_A5 BUS_A6 BUS_A7 BUS_A8 BUS_A9 BUS_A10 BUS_A11 BUS_A12 BUS_A13 BUS_A14 BUS_A15 BUS_A16 BUS_A17 BUS_A18 BUS_A19 BUS_A20 BUS_A21 BUS_A22 BUS_A23 BUS_A24
net class CLKS: BUS_SDRAM_CLK BUS_SDRAM_FEEDBACK FPGA_CLK FPGA_CLK1 ONE_WIRE_DB_PB REF_CLK UGCLK0 UGCLK1 UGCLK2
component class U_Bypass_3V3: C42 C43 C44 C45 C46 C47 C48 C49 C50 C51 C52 C53 C54 C55 C56 C57 C58 C59 C60 C61 C62 C63 C64 C65 C66 C67 C68 C69 C70 C71 C72 C73 C74 C75 C76 C77 C78 C79 C80 C81 C82 C83 C84 C85 C86 C87 C88 C89 C90 C91 C92 C93 C94 C95 C96 C97 C98 C99 C100 C101 C102 C102_FP C103 C103_FP C104 C104_FP C105 C105_FP C106_FP
component class U_MotherBoardConnectors: HDR_B1 HDR_L HDR_L1 HDR_T1 NT1
component class U_FPGA: D1 F1 J1_U NT2 NT3 NT4 NT5 NT6 NT7 R1HD R2HD R3 R3HD R4 R4HD R5 R6 R7 R8 R9 R10 R11 R12 R13 R14 R15 R16 R17 U4
net class BUS_D[31..0]: BUS_D0 BUS_D1 BUS_D2 BUS_D3 BUS_D4 BUS_D5 BUS_D6 BUS_D7 BUS_D8 BUS_D9 BUS_D10 BUS_D11 BUS_D12 BUS_D13 BUS_D14 BUS_D15 BUS_D16 BUS_D17 BUS_D18 BUS_D19 BUS_D20 BUS_D21 BUS_D22 BUS_D23 BUS_D24 BUS_D25 BUS_D26 BUS_D27 BUS_D28 BUS_D29 BUS_D30 BUS_D31
net class BUS_NBE[3..0]: BUS_NBE0 BUS_NBE1 BUS_NBE2 BUS_NBE3
net class DIP[7..0]: DIP0 DIP1 DIP2 DIP3 DIP4 DIP5 DIP6 DIP7
net class FPGA_ID[3..0]: FPGA_ID0 FPGA_ID1 FPGA_ID2 FPGA_ID3
net class FPGA_M[2..0]: FPGA_M0 FPGA_M1 FPGA_M2
net class IO[35..0]: IO0 IO1 IO2 IO3 IO4 IO5 IO6 IO7 IO8 IO9 IO10 IO11 IO12 IO13 IO14 IO15 IO16 IO17 IO18 IO19 IO20 IO21 IO22 IO23 IO24 IO25 IO26 IO27 IO28 IO29 IO30 IO31 IO32 IO33 IO34 IO35
net class LED[7..0]: LED0 LED1 LED2 LED3 LED4 LED5 LED6 LED7
net class SW[4..0]: SW0 SW1 SW2 SW3 SW4
differential pair class DIFF_IN: DIFF_RX0 DIFF_RX1 DIFF_RX2 DIFF_RX3
differential pair class DIFF_OUT: DIFF_TX0 DIFF_TX1 DIFF_TX2 DIFF_TX3
net class PWRNET: 1V2 2V5 3V3 5V0 AGND GND
net class UGCLK[2..0]: UGCLK0 UGCLK1 UGCLK2
component class U_MOUNTS: "Altium Logo Bot1" "Altium Logo Top1" LB1 MH1 MH2 MH3
component class U_Bypass_1V2: C3 C4 C5 C6 C7 C8 C9 C10 C11 C12 C13 C14 C15 C16 C17 C18 C19 C20 C21 C22
component class U_Bypass_2V5: C23 C24 C25 C26 C27 C28 C29 C30 C31 C32 C33 C34 C35 C36 C37 C38 C39 C40 C41
component class U_DB30_Hardware_Kit: PCB1

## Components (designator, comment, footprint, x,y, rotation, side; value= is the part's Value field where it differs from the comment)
"Altium Logo Bot1" "Altium" Logo-Altium 2177.16,129.92 r180 bottom
"Altium Logo Top1" "Altium" Logo-Altium 1051.18,129.92 r0 top
C1 "0.1uF 16V" CAPC1005-STAR#1 2807.08,3015.74 r180 bottom
C2 "10nF 16V" CAPC1005-STAR#1 2807.08,2968.5 r0 bottom
C3 "220uF 10V" CAPC7343-STAR 2492.13,1551.18 r0 bottom (schematic designator C1)
C4 "10uF 10V" CAPC2012-STAR 889.76,1551.18 r90 bottom (schematic designator C2)
C5 "10uF 10V" CAPC2012-STAR 1606.3,838.58 r0 bottom (schematic designator C3)
C6 "10uF 10V" CAPC2012-STAR 2153.54,1551.18 r90 bottom (schematic designator C4)
C7 "0.1uF 16V" CAPC1005-STAR#1 1689.96,1256.89 r180 bottom (schematic designator C5)
C8 "0.1uF 16V" CAPC1005-STAR#1 1771.65,1306.1 r90 bottom (schematic designator C6)
C9 "0.1uF 16V" CAPC1005-STAR#1 1356.3,1253.94 r0 bottom (schematic designator C7)
C10 "0.1uF 16V" CAPC1005-STAR#1 1771.65,1638.78 r270 bottom (schematic designator C8)
C11 "0.1uF 16V" CAPC1005-STAR#1 1306.1,1305.12 r90 bottom (schematic designator C9)
C12 "0.1uF 16V" CAPC1005-STAR#2 1689.96,1687.01 r180 bottom (schematic designator C10)
C13 "0.1uF 16V" CAPC1005-STAR#1 1275.59,1638.78 r270 bottom (schematic designator C11)
C14 "0.1uF 16V" CAPC1005-STAR#2 1357.28,1687.01 r0 bottom (schematic designator C12)
C15 "10nF 16V" CAPC1005-STAR#1 1689.96,1224.41 r180 bottom (schematic designator C13)
C16 "10nF 16V" CAPC1005-STAR#1 1738.19,1306.1 r90 bottom (schematic designator C14)
C17 "10nF 16V" CAPC1005-STAR#2 1738.19,1638.78 r270 bottom (schematic designator C15)
C18 "10nF 16V" CAPC1005-STAR#1 1357.28,1720.47 r0 bottom (schematic designator C16)
C19 "10nF 16V" CAPC1005-STAR#1 1275.59,1305.12 r90 bottom (schematic designator C17)
C20 "10nF 16V" CAPC1005-STAR#1 1356.3,1224.41 r0 bottom (schematic designator C18)
C21 "10nF 16V" CAPC1005-STAR#1 1689.96,1720.47 r180 bottom (schematic designator C19)
C22 "10nF 16V" CAPC1005-STAR#2 1309.05,1638.78 r270 bottom (schematic designator C20)
C23 "220uF 10V" CAPC7343-STAR 767.72,818.9 r180 top (schematic designator C1)
C24 "10uF 10V" CAPC2012-STAR 2586.61,2405.51 r90 top (schematic designator C2)
C25 "10uF 10V" CAPC2012-STAR 1397.64,2106.29 r180 bottom (schematic designator C3)
C26 "0.1uF 16V" CAPC1005-STAR#1 1728.34,2035.43 r90 bottom (schematic designator C4)
C27 "0.1uF 16V" CAPC1005-STAR#1 2073.29,1678.7 r0 bottom (schematic designator C5)
C28 "0.1uF 16V" CAPC1005-STAR#1 960.63,1267.71 r180 bottom (schematic designator C6)
C29 "0.1uF 16V" CAPC1005-STAR#1 1318.89,2035.43 r90 bottom (schematic designator C7)
C30 "0.1uF 16V" CAPC1005-STAR#1 1728.34,909.45 r270 bottom (schematic designator C8)
C31 "10nF 16V" CAPC1005-STAR#1 1965.14,981.04 r90 bottom (schematic designator C9)
C32 "10nF 16V" CAPC1005-STAR#1 960.63,1677.16 r180 bottom (schematic designator C10)
C33 "10nF 16V" CAPC1005-STAR#1 1082.1,1963.84 r270 bottom (schematic designator C11)
C34 "10nF 16V" CAPC1005-STAR#1 1963.99,1963.84 r270 bottom (schematic designator C12)
C35 "10nF 16V" CAPC1005-STAR#1 1032.22,1030.92 r0 bottom (schematic designator C13)
C36 "10nF 16V" CAPC1005-STAR#1 2015.02,1032.07 r180 bottom (schematic designator C14)
C37 "10nF 16V" CAPC1005-STAR#1 2015.02,1913.96 r180 bottom (schematic designator C15)
C38 "10nF 16V" CAPC1005-STAR#1 1083.25,981.04 r90 bottom (schematic designator C16)
C39 "10nF 16V" CAPC1005-STAR#1 2086.61,1267.71 r0 bottom (schematic designator C17)
C40 "10nF 16V" CAPC1005-STAR#1 1318.89,909.45 r270 bottom (schematic designator C18)
C41 "10nF 16V" CAPC1005-STAR#1 1032.22,1912.81 r0 bottom (schematic designator C19)
C42 "10uF 10V" CAPC2012-STAR 1240.15,2106.29 r0 bottom (schematic designator C1)
C43 "10uF 10V" CAPC2012-STAR 889.76,1716.53 r270 bottom (schematic designator C2)
C44 "10uF 10V" CAPC2012-STAR 1807.21,2105.29 r180 bottom (schematic designator C3)
C45 "10uF 10V" CAPC2012-STAR 889.76,1188.97 r90 bottom (schematic designator C4)
C46 "10uF 10V" CAPC2012-STAR 2153.54,1708.66 r270 bottom (schematic designator C5)
C47 "10uF 10V" CAPC2012-STAR 2157.48,1185.04 r90 bottom (schematic designator C6)
C48 "10uF 10V" CAPC2012-STAR 1771.65,838.58 r180 bottom (schematic designator C7)
C49 "10uF 10V" CAPC2012-STAR 1236.22,838.58 r0 bottom (schematic designator C8)
C50 "0.1uF 16V" CAPC1005-STAR#1 2015.74,1173.23 r0 bottom (schematic designator C9)
C51 "0.1uF 16V" CAPC1005-STAR#1 1779.52,980.31 r270 bottom (schematic designator C10)
C52 "0.1uF 16V" CAPC1005-STAR#1 1622.04,980.31 r270 bottom (schematic designator C11)
C53 "0.1uF 16V" CAPC1005-STAR#1 1031.49,1334.64 r180 bottom (schematic designator C12)
C54 "0.1uF 16V" CAPC1005-STAR#1 2015.74,1724.41 r0 bottom (schematic designator C13)
C55 "0.1uF 16V" CAPC1005-STAR#1 2015.74,1374.01 r0 bottom (schematic designator C14)
C56 "0.1uF 16V" CAPC1005-STAR#1 1031.49,1220.47 r180 bottom (schematic designator C15)
C57 "0.1uF 16V" CAPC1005-STAR#1 1429.13,980.31 r270 bottom (schematic designator C16)
C58 "0.1uF 16V" CAPC1005-STAR#1 1031.49,1570.86 r180 bottom (schematic designator C17)
C59 "0.1uF 16V" CAPC1005-STAR#1 1228.34,1964.56 r90 bottom (schematic designator C18)
C60 "0.1uF 16V" CAPC1005-STAR#1 1822.83,1964.56 r90 bottom (schematic designator C19)
C61 "0.1uF 16V" CAPC1005-STAR#1 1031.49,1728.34 r180 bottom (schematic designator C20)
C62 "0.1uF 16V" CAPC1005-STAR#1 1228.34,980.31 r270 bottom (schematic designator C21)
C63 "0.1uF 16V" CAPC1005-STAR#1 2015.74,1566.93 r0 bottom (schematic designator C22)
C64 "0.1uF 16V" CAPC1005-STAR#1 1665.35,1964.56 r90 bottom (schematic designator C23)
C65 "0.1uF 16V" CAPC1005-STAR#1 1429.13,1964.56 r90 bottom (schematic designator C24)
C66 "10nF 16V" CAPC1005-STAR#1 1366.14,1457.68 r0 bottom (schematic designator C25)
C67 "10nF 16V" CAPC1005-STAR#1 1508.86,1629.92 r270 bottom (schematic designator C26)
C68 "10nF 16V" CAPC1005-STAR#1 1779.52,1964.56 r90 bottom (schematic designator C27)
C69 "10nF 16V" CAPC1005-STAR#1 1822.83,980.31 r270 bottom (schematic designator C28)
C70 "10nF 16V" CAPC1005-STAR#1 1271.65,1964.56 r90 bottom (schematic designator C29)
C71 "10nF 16V" CAPC1005-STAR#1 2015.74,1610.23 r0 bottom (schematic designator C30)
C72 "10nF 16V" CAPC1005-STAR#1 1681.1,1487.2 r180 bottom (schematic designator C31)
C73 "10nF 16V" CAPC1005-STAR#1 1508.86,1553.15 r90 bottom (schematic designator C32)
C74 "10nF 16V" CAPC1005-STAR#1 1538.39,1553.15 r90 bottom (schematic designator C33)
C75 "10nF 16V" CAPC1005-STAR#1 1538.39,1629.92 r270 bottom (schematic designator C34)
C76 "10nF 16V" CAPC1005-STAR#1 1758.86,1457.68 r0 bottom (schematic designator C35)
C77 "10nF 16V" CAPC1005-STAR#1 1681.1,1457.68 r180 bottom (schematic designator C36)
C78 "10nF 16V" CAPC1005-STAR#1 1604.33,1487.2 r0 bottom (schematic designator C37)
C79 "10nF 16V" CAPC1005-STAR#1 1289.37,1487.2 r180 bottom (schematic designator C38)
C80 "10nF 16V" CAPC1005-STAR#1 1508.86,1706.69 r90 bottom (schematic designator C39)
C81 "10nF 16V" CAPC1005-STAR#1 1289.37,1457.68 r180 bottom (schematic designator C40)
C82 "10nF 16V" CAPC1005-STAR#1 1508.86,1390.75 r270 bottom (schematic designator C41)
C83 "10nF 16V" CAPC1005-STAR#1 1385.82,980.31 r270 bottom (schematic designator C42)
C84 "10nF 16V" CAPC1005-STAR#1 1031.49,1177.16 r180 bottom (schematic designator C43)
C85 "10nF 16V" CAPC1005-STAR#1 1271.65,980.31 r270 bottom (schematic designator C44)
C86 "10nF 16V" CAPC1005-STAR#1 1508.86,1237.2 r270 bottom (schematic designator C45)
C87 "10nF 16V" CAPC1005-STAR#1 1538.39,1237.2 r270 bottom (schematic designator C46)
C88 "10nF 16V" CAPC1005-STAR#1 1508.86,1313.98 r90 bottom (schematic designator C47)
C89 "10nF 16V" CAPC1005-STAR#1 2015.74,1767.71 r0 bottom (schematic designator C48)
C90 "10nF 16V" CAPC1005-STAR#1 1604.33,1457.68 r0 bottom (schematic designator C49)
C91 "10nF 16V" CAPC1005-STAR#1 1665.35,980.31 r270 bottom (schematic designator C50)
C92 "10nF 16V" CAPC1005-STAR#1 1538.39,1313.98 r90 bottom (schematic designator C51)
C93 "10nF 16V" CAPC1005-STAR#1 1366.14,1487.2 r0 bottom (schematic designator C52)
C94 "10nF 16V" CAPC1005-STAR#1 1442.91,1487.2 r180 bottom (schematic designator C53)
C95 "10nF 16V" CAPC1005-STAR#1 1442.91,1457.68 r180 bottom (schematic designator C54)
C96 "10nF 16V" CAPC1005-STAR#1 1758.86,1487.2 r0 bottom (schematic designator C55)
C97 "10nF 16V" CAPC1005-STAR#1 1538.39,1706.69 r90 bottom (schematic designator C56)
C98 "10nF 16V" CAPC1005-STAR#1 1538.39,1390.75 r270 bottom (schematic designator C57)
C99 "10nF 16V" CAPC1005-STAR#1 1622.04,1964.56 r90 bottom (schematic designator C58)
C100 "10nF 16V" CAPC1005-STAR#1 1385.82,1964.56 r90 bottom (schematic designator C59)
C101 "10nF 16V" CAPC1005-STAR#1 1031.49,1377.95 r180 bottom (schematic designator C60)
C102 "10nF 16V" CAPC1005-STAR#1 1031.49,1614.17 r180 bottom (schematic designator C61)
C103 "10nF 16V" CAPC1005-STAR#1 2015.74,1216.53 r0 bottom (schematic designator C62)
C104 "10nF 16V" CAPC1005-STAR#1 1031.49,1771.65 r180 bottom (schematic designator C63)
C105 "10nF 16V" CAPC1005-STAR#1 2015.74,1330.71 r0 bottom (schematic designator C64)
C106 "220uF 10V" CAPC7343-STAR 681.1,1255.9 r270 bottom (schematic designator C1_MB)
C107 "220uF 10V" CAPC7343-STAR 1870.07,2862.2 r180 bottom (schematic designator C2_MB)
C108 "0.1uF 16V" CAPC1005-STAR#1 1259.84,236.22 r0 bottom (schematic designator C1_SL)
C109 "0.1uF 16V" CAPC1005-STAR#1 2370.07,2799.21 r180 bottom (schematic designator C1)
C110 "0.1uF 16V" CAPC1005-STAR#1 2263.78,3233.27 r180 bottom (schematic designator C2)
C111 "10nF 16V" CAPC1005-STAR#1 2185.04,2969.49 r270 bottom (schematic designator C3)
C112 "10nF 16V" CAPC1005-STAR#1 2370.07,2842.51 r180 bottom (schematic designator C4)
C113 "10nF 16V" CAPC1005-STAR#1 2263.78,3186.02 r180 bottom (schematic designator C5)
C114 "0.1uF 16V" CAPC1005-STAR#1 2141.73,2969.49 r270 bottom (schematic designator C6)
C115 "10uF 10V" CAPC2012-STAR 2765.75,3087.59 r0 bottom (schematic designator C23_CM)
C116 "10uF 10V" CAPC2012-STAR 2216.53,3986.21 r270 bottom (schematic designator C24_CM)
C117 "470pF 50V" CAPC1005-STAR#1 2944.88,1740.15 r90 top (schematic designator C2_PS)
C118 "2.2uF 10V" CAPC1608-STAR 2456.69,1692.91 r180 top (schematic designator C4_PS)
C119 "220uF 10V" CAPC7343-STAR 2814.95,2149.6 r180 top (schematic designator C3_PS)
C120 "10uF 10V" CAPC2012-STAR 2988.18,1425.19 r270 top (schematic designator C5_PS)
C121 "22uF 10V" CAPC3225-STAR 2748.03,1503.93 r180 top (schematic designator C6_PS)
C122 "10uF 10V" CAPC2012-STAR 3118.1,1795.27 r270 top (schematic designator C8_PS)
C123 "22uF 10V" CAPC3225-STAR 2637.79,1976.37 r180 top (schematic designator C1_PS)
C124 "1uF 25V" CAPC3216-STAR 2448.81,1783.46 r0 top (schematic designator C7_PS)
C125 "2.2uF 10V" CAPC1608-STAR 1744.09,2401.57 r180 top (schematic designator C3_LD)
C126 "2.2uF 10V" CAPC1608-STAR 1657.48,2515.74 r270 top (schematic designator C1_LD)
C127 "0.033uF 10V" CAPC1005-STAR#1 2015.74,2547.24 r0 top (schematic designator C2_LD)
C128 "0.1uF 16V" CAPC1005-STAR#1 2149.6,4007.87 r270 top (schematic designator C1)
C129 "0.1uF 16V" CAPC1005-STAR#1 1535.43,3374.01 r180 top (schematic designator C2)
C130 "0.1uF 16V" CAPC1005-STAR#1 1279.52,3405.5 r180 bottom (schematic designator C3)
C131 "0.1uF 16V" CAPC1005-STAR#1 1803.15,3999.99 r90 bottom (schematic designator C4)
C132 "10nF 16V" CAPC1005-STAR#1 1440.94,3980.31 r180 top (schematic designator C5)
C133 "10nF 16V" CAPC1005-STAR#1 1629.92,3980.31 r180 top (schematic designator C6)
C134 "10nF 16V" CAPC1005-STAR#1 2039.37,3374.01 r180 bottom (schematic designator C7)
C135 "10nF 16V" CAPC1005-STAR#1 1850.39,3374.01 r180 bottom (schematic designator C8)
C136 "0.1uF 16V" CAPC1005-STAR#1 2915.44,1059.04 r90 top (schematic designator C1_SM)
C137 "0.1uF 16V" CAPC1005-STAR#1 2309.14,1055.11 r270 top (schematic designator C2_SM)
C138 "10nF 16V" CAPC1005-STAR#1 2915.44,980.3 r270 top (schematic designator C3_SM)
C139 "10nF 16V" CAPC1005-STAR#1 2259.84,1055.12 r270 top (schematic designator C4_SM)
C140 "0.1uF 16V" CAPC1005-STAR#1 2391.82,980.3 r270 bottom (schematic designator C1_SM)
C141 "0.1uF 16V" CAPC1005-STAR#1 3007.87,1133.86 r90 bottom (schematic designator C2_SM)
C142 "10nF 16V" CAPC1005-STAR#1 2391.82,1062.98 r90 bottom (schematic designator C3_SM)
C143 "10nF 16V" CAPC1005-STAR#1 3007.87,1055.12 r270 bottom (schematic designator C4_SM)
C144 "0.1uF 16V" CAPC1005-STAR#1 2604.05,3326.76 r0 top (schematic designator C1)
C145 "0.1uF 16V" CAPC1005-STAR#1 2602.36,4027.55 r180 top (schematic designator C2)
C146 "0.1uF 16V" CAPC1005-STAR#1 2602.36,3330.7 r0 bottom (schematic designator C3)
C147 "0.1uF 16V" CAPC1005-STAR#1 2665.35,4027.55 r0 bottom (schematic designator C4)
C148 "10nF 16V" CAPC1005-STAR#1 2604.05,3370.07 r0 top (schematic designator C5)
C149 "10nF 16V" CAPC1005-STAR#1 2602.08,3984.25 r180 top (schematic designator C6)
C150 "10nF 16V" CAPC1005-STAR#1 2602.36,3370.07 r0 bottom (schematic designator C7)
C151 "10nF 16V" CAPC1005-STAR#1 2665.35,3984.25 r0 bottom (schematic designator C8)
HDR_B1 "MOLEX - 54075-1009" 54075 1893.7,472.44 r0 bottom locked (schematic designator HDR_B)
HDR_L1 "MOLEX - 54075-1009" 54075 307.09,1472.44 r270 bottom locked (schematic designator HDR_L)
HDR_T1 "MOLEX - 54075-1009" 54075 1893.7,2472.44 r0 bottom locked (schematic designator HDR_T)
L1 "2u2, 15A, 4R2, SMD" IND-EPCOS-SMD-B82559 2944.88,1649.6 r90 bottom (schematic designator L1_PS)
LED1 "GREEN" LED2012-STAR 1261.81,169.29 r180 top (schematic designator LED2_SL)
LED2 "RED" LED2012-STAR 1974.41,169.29 r180 top (schematic designator LED1_SL)
MH1 "MOUNTING HOLE 3MM" MOUNTING_HOLE_3MM 1618.11,129.92 r180 top locked
MH2 "MOUNTING HOLE 3MM" MOUNTING_HOLE_3MM 129.92,4326.77 r180 top locked
MH3 "MOUNTING HOLE 3MM" MOUNTING_HOLE_3MM 3106.3,4326.77 r180 top locked
NT1 "Net Tie SMT2" NETTIE-SMT2-8X8 1626.22,2700.43 r90 bottom net-tie
NT2 "Net Tie SMT2" NETTIE-SMT2-8X8 1464.21,258.62 r0 bottom net-tie (schematic designator NT6)
NT3 "Net Tie SMT2" NETTIE-SMT2-8X8 1550.94,2165 r90 top net-tie (schematic designator NT8)
NT4 "Net Tie SMT2" NETTIE-SMT2-8X8 1752.2,2680.73 r90 bottom net-tie (schematic designator NT2)
NT5 "Net Tie SMT2" NETTIE-SMT2-8X8 1720.7,2680.73 r90 bottom net-tie (schematic designator NT3)
NT6 "Net Tie SMT2" NETTIE-SMT2-8X8 1689.21,2680.74 r90 bottom net-tie (schematic designator NT4)
NT7 "Net Tie SMT2" NETTIE-SMT2-8X8 1657.71,2680.74 r90 bottom net-tie (schematic designator NT5)
NT8 "Net Tie SMT2" NETTIE-SMT2-8X8 2519.44,1982.83 r90 top net-tie (schematic designator NT7)
PBFREE "" LEAD_FREE_S 292.32,3631.89 r180 bottom
R1 "270R 1%" RESC1005-STAR 1248.03,169.29 r180 bottom (schematic designator R2_SL)
R2 "270R 1%" RESC1005-STAR 1974.41,169.29 r180 bottom (schematic designator R1_SL)
R3 "4K7 1%" RESC1005-STAR 866.14,2145.66 r180 bottom (schematic designator R1)
R4 "100R 1%" RESC1005-STAR 984.25,2145.66 r0 bottom (schematic designator R7)
R5 "4K7 1%" RESC1005-STAR 2129.92,2106.29 r90 bottom (schematic designator R2)
R6 "100R 1%" RESC1005-STAR 1968.5,2106.29 r270 bottom (schematic designator R8)
R7 "100R 1%" RESC1005-STAR 2047.24,2106.3 r270 bottom (schematic designator R9)
R8 "100R 1%" RESC1005-STAR 2129.92,2023.62 r270 bottom (schematic designator R10)
R9 "4K7 1%" RESC1005-STAR 2039.37,866.14 r180 bottom (schematic designator R3)
R10 "100R 1%" RESC1005-STAR 984.25,2094.48 r180 bottom (schematic designator R12)
R11 "100R 1%" RESC1005-STAR 885.82,925.2 r0 bottom (schematic designator R14)
R12 "4K7 1%" RESC1005-STAR 2165.35,925.2 r180 bottom (schematic designator R4)
R13 "100R 1%" RESC1005-STAR 885.82,968.5 r0 bottom (schematic designator R18)
R14 "100R 1%" RESC1005-STAR 885.82,881.89 r0 bottom (schematic designator R23)
R15 "100R 1%" RESC1005-STAR 866.14,2094.48 r180 bottom (schematic designator R24)
R16 "100R 1%" RESC1005-STAR 2165.35,984.25 r180 bottom (schematic designator R22)
R17 "100R 1%" RESC1005-STAR 2165.35,1043.31 r180 bottom (schematic designator R20)
R18 "100K 1%" RESC1005-STAR 1826.77,2358.26 r180 top (schematic designator R1T)
R19 "10R 1%" RESC1005-STAR 2492.12,1622.04 r90 top (schematic designator R2_PS)
R20 "2K7 1%" RESC1005-STAR 2787.4,1866.14 r0 top (schematic designator R1_PS)
R21 "27K 1%" RESC1005-STAR 2889.76,1866.14 r0 top (schematic designator R3_PS)
R22 "2K7 1%" RESC1005-STAR 2992.12,1866.14 r0 top (schematic designator R4_PS)
R23 "100K 1%" RESC1005-STAR 2992.12,1814.96 r0 top (schematic designator R5_PS)
R24 "100K 1%" RESC1005-STAR 1720.47,2637.79 r0 top (schematic designator R1_LD)
R25 "100K 1%" RESC1005-STAR 1854.33,2413.38 r180 top (schematic designator R2_LD)
RN1 "RESNET 4 x 100R" RESNET-1005X4 1662.98,3301.18 r90 bottom (schematic designator RN33)
RN2 "RESNET 4 x 100R" RESNET-1005X4 1366.74,3301.18 r90 bottom (schematic designator RN35)
RN3 "RESNET 4 x 100R" RESNET-1005X4 1559.65,4025.59 r90 bottom (schematic designator RN37)
RN4 "RESNET 4 x 100R" RESNET-1005X4 1804.73,3301.18 r270 bottom (schematic designator RN34)
RN5 "RESNET 4 x 100R" RESNET-1005X4 1701.39,4025.59 r270 bottom (schematic designator RN38)
RN6 "RESNET 4 x 100R" RESNET-1005X4 1508.47,3301.18 r270 bottom (schematic designator RN36)
TP1 "GND" TestPin 2875.71,3138.67 r0 top (schematic designator TP0)
TP2 "3V3" TestPin 2875.71,3038.67 r0 top (schematic designator TP1)
TP3 "2V5" TestPin 2875.71,2938.67 r0 top (schematic designator TP2)
TP4 "5V0" TestPin 2875.71,2838.67 r0 top (schematic designator TP3)
TP5 "1V2" TestPin 2875.71,2738.67 r0 top (schematic designator TP4)
U1 "DS2406" TSOC6 2712.59,2846.45 r90 bottom
U2 "SN74LVC1G04DBV" SOT95P280-5 1397.64,165.35 r0 bottom (schematic designator U1_SL)
U3 "S29GL256N11FFIV10" BGA100P8X8-64 2370.08,3036.42 r180 top locked (schematic designator U1)
U4 "XC3S1500-4FG676C" BGA100P26X26-676 1523.62,1472.44 r0 top locked (schematic designator U1)
U5 "MAX1831EEE" SOP63P602-16 2708.58,1720.75 r180 top locked (schematic designator U1_PS)
U6 "MAX8860EUA18+" SOP65P490-8 1826.77,2507.87 r0 top (schematic designator U11)
U7 "SDRAM-16Mx16" TSOP80P1176-54 1740.16,3677.16 r0 top (schematic designator U1)
U8 "SDRAM-16Mx16" TSOP80P1176-54 1740.16,3677.17 r180 bottom locked (schematic designator U2)
U9 "SRAM-256Kx16" TSOP80P1176-44 2612.3,1059.05 r90 top (schematic designator U1_SM)
U10 "SRAM-256Kx16" TSOP80P1176-44 2702.84,1059.04 r90 bottom (schematic designator U1_SM)
U11 "SRAM-256Kx16" TSOP80P1176-44 2602.36,3677.16 r0 top (schematic designator U1)
U12 "SRAM-256Kx16" TSOP80P1176-44 2665.35,3677.17 r180 bottom locked (schematic designator U2)

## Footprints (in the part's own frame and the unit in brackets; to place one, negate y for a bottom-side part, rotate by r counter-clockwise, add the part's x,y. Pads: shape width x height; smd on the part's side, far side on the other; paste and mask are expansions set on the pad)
54075 [mm]
  rect 0.5x1.9 smd: 1(-19.6,3.4) 2(-19.6,-3.4) 3(-18.8,3.4) 4(-18.8,-3.4) 5(-18,3.4) 6(-18,-3.4) 7(-17.2,3.4) 8(-17.2,-3.4) 9(-16.4,3.4) 10(-16.4,-3.4) 11(-15.6,3.4) 12(-15.6,-3.4) 13(-14.8,3.4) 14(-14.8,-3.4) 15(-14,3.4) 16(-14,-3.4) 17(-13.2,3.4) 18(-13.2,-3.4) 19(-12.4,3.4) 20(-12.4,-3.4) 21(-11.6,3.4) 22(-11.6,-3.4) 23(-10.8,3.4) 24(-10.8,-3.4) 25(-10,3.4) 26(-10,-3.4) 27(-9.2,3.4) 28(-9.2,-3.4) 29(-8.4,3.4) 30(-8.4,-3.4) 31(-7.6,3.4) 32(-7.6,-3.4) 33(-6.8,3.4) 34(-6.8,-3.4) 35(-6,3.4) 36(-6,-3.4) 37(-5.2,3.4) 38(-5.2,-3.4) 39(-4.4,3.4) 40(-4.4,-3.4) 41(-3.6,3.4) 42(-3.6,-3.4) 43(-2.8,3.4) 44(-2.8,-3.4) 45(-2,3.4) 46(-2,-3.4) 47(-1.2,3.4) 48(-1.2,-3.4) 49(-0.4,3.4) 50(-0.4,-3.4) 51(0.4,3.4) 52(0.4,-3.4) 53(1.2,3.4) 54(1.2,-3.4) 55(2,3.4) 56(2,-3.4) 57(2.8,3.4) 58(2.8,-3.4) 59(3.6,3.4) 60(3.6,-3.4) 61(4.4,3.4) 62(4.4,-3.4) 63(5.2,3.4) 64(5.2,-3.4) 65(6,3.4) 66(6,-3.4) 67(6.8,3.4) 68(6.8,-3.4) 69(7.6,3.4) 70(7.6,-3.4) 71(8.4,3.4) 72(8.4,-3.4) 73(9.2,3.4) 74(9.2,-3.4) 75(10,3.4) 76(10,-3.4) 77(10.8,3.4) 78(10.8,-3.4) 79(11.6,3.4) 80(11.6,-3.4) 81(12.4,3.4) 82(12.4,-3.4) 83(13.2,3.4) 84(13.2,-3.4) 85(14,3.4) 86(14,-3.4) 87(14.8,3.4) 88(14.8,-3.4) 89(15.6,3.4) 90(15.6,-3.4) 91(16.4,3.4) 92(16.4,-3.4) 93(17.2,3.4) 94(17.2,-3.4) 95(18,3.4) 96(18,-3.4) 97(18.8,3.4) 98(18.8,-3.4) 99(19.6,3.4) 100(19.6,-3.4)
  round 1.6 hole 0.7: MH1(-26.7,4.2) MH2(-25.9,-4.2) MH3(26.7,4.2) MH4(25.9,-4.2)
  round 4.8 hole 5.1 unplated: MH5(-26.3,0) MH6(26.3,0)
  Top Layer keep-out region: -20.15,2.15 20.15,2.15 20.15,-2.15 -20.15,-2.15
  silkscreen extent -30.35,-4.4 30.35,5.02, body extent -30.35,-4.4 30.35,4.4, height 3.6
BGA100P8X8-64 [mm] "AMD 64-Ball Fortfied Ball grid Array (FBGA)"
  round 0.5 smd: A1(-3.5,-3.5) A2(-3.5,-2.5) A3(-3.5,-1.5) A4(-3.5,-0.5) A5(-3.5,0.5) A6(-3.5,1.5) A7(-3.5,2.5) A8(-3.5,3.5) B1(-2.5,-3.5) B2(-2.5,-2.5) B3(-2.5,-1.5) B4(-2.5,-0.5) B5(-2.5,0.5) B6(-2.5,1.5) B7(-2.5,2.5) B8(-2.5,3.5) C1(-1.5,-3.5) C2(-1.5,-2.5) C3(-1.5,-1.5) C4(-1.5,-0.5) C5(-1.5,0.5) C6(-1.5,1.5) C7(-1.5,2.5) C8(-1.5,3.5) D1(-0.5,-3.5) D2(-0.5,-2.5) D3(-0.5,-1.5) D4(-0.5,-0.5) D5(-0.5,0.5) D6(-0.5,1.5) D7(-0.5,2.5) D8(-0.5,3.5) E1(0.5,-3.5) E2(0.5,-2.5) E3(0.5,-1.5) E4(0.5,-0.5) E5(0.5,0.5) E6(0.5,1.5) E7(0.5,2.5) E8(0.5,3.5) F1(1.5,-3.5) F2(1.5,-2.5) F3(1.5,-1.5) F4(1.5,-0.5) F5(1.5,0.5) F6(1.5,1.5) F7(1.5,2.5) F8(1.5,3.5) G1(2.5,-3.5) G2(2.5,-2.5) G3(2.5,-1.5) G4(2.5,-0.5) G5(2.5,0.5) G6(2.5,1.5) G7(2.5,2.5) G8(2.5,3.5) H1(3.5,-3.5) H2(3.5,-2.5) H3(3.5,-1.5) H4(3.5,-0.5) H5(3.5,0.5) H6(3.5,1.5) H7(3.5,2.5) H8(3.5,3.5)
  silkscreen extent -6.5,-6.32 6.5,5.5, body extent -6.35,-5.4 6.41,5.36, height 1
BGA100P26X26-676 [mm]
  round 0.5 smd: A1(-12.5,12.5) A2(-11.5,12.5) A3(-10.5,12.5) A4(-9.5,12.5) A5(-8.5,12.5) A6(-7.5,12.5) A7(-6.5,12.5) A8(-5.5,12.5) A9(-4.5,12.5) A10(-3.5,12.5) A11(-2.5,12.5) A12(-1.5,12.5) A13(-0.5,12.5) A14(0.5,12.5) A15(1.5,12.5) A16(2.5,12.5) A17(3.5,12.5) A18(4.5,12.5) A19(5.5,12.5) A20(6.5,12.5) A21(7.5,12.5) A22(8.5,12.5) A23(9.5,12.5) A24(10.5,12.5) A25(11.5,12.5) A26(12.5,12.5) AA1(-12.5,-7.5) AA2(-11.5,-7.5) AA3(-10.5,-7.5) AA4(-9.5,-7.5) AA5(-8.5,-7.5) AA6(-7.5,-7.5) AA7(-6.5,-7.5) AA8(-5.5,-7.5) AA9(-4.5,-7.5) AA10(-3.5,-7.5) AA11(-2.5,-7.5) AA12(-1.5,-7.5) AA13(-0.5,-7.5) AA14(0.5,-7.5) AA15(1.5,-7.5) AA16(2.5,-7.5) AA17(3.5,-7.5) AA18(4.5,-7.5) AA19(5.5,-7.5) AA20(6.5,-7.5) AA21(7.5,-7.5) AA22(8.5,-7.5) AA23(9.5,-7.5) AA24(10.5,-7.5) AA25(11.5,-7.5) AA26(12.5,-7.5) AB1(-12.5,-8.5) AB2(-11.5,-8.5) AB3(-10.5,-8.5) AB4(-9.5,-8.5) AB5(-8.5,-8.5) AB6(-7.5,-8.5) AB7(-6.5,-8.5) AB8(-5.5,-8.5) AB9(-4.5,-8.5) AB10(-3.5,-8.5) AB11(-2.5,-8.5) AB12(-1.5,-8.5) AB13(-0.5,-8.5) AB14(0.5,-8.5) AB15(1.5,-8.5) AB16(2.5,-8.5) AB17(3.5,-8.5) AB18(4.5,-8.5) AB19(5.5,-8.5) AB20(6.5,-8.5) AB21(7.5,-8.5) AB22(8.5,-8.5) AB23(9.5,-8.5) AB24(10.5,-8.5) AB25(11.5,-8.5) AB26(12.5,-8.5) AC1(-12.5,-9.5) AC2(-11.5,-9.5) AC3(-10.5,-9.5) AC4(-9.5,-9.5) AC5(-8.5,-9.5) AC6(-7.5,-9.5) AC7(-6.5,-9.5) AC8(-5.5,-9.5) AC9(-4.5,-9.5) AC10(-3.5,-9.5) AC11(-2.5,-9.5) AC12(-1.5,-9.5) AC13(-0.5,-9.5) AC14(0.5,-9.5) AC15(1.5,-9.5) AC16(2.5,-9.5) AC17(3.5,-9.5) AC18(4.5,-9.5) AC19(5.5,-9.5) AC20(6.5,-9.5) AC21(7.5,-9.5) AC22(8.5,-9.5) AC23(9.5,-9.5) AC24(10.5,-9.5) AC25(11.5,-9.5) AC26(12.5,-9.5) AD1(-12.5,-10.5) AD2(-11.5,-10.5) AD3(-10.5,-10.5) AD4(-9.5,-10.5) AD5(-8.5,-10.5) AD6(-7.5,-10.5) AD7(-6.5,-10.5) AD8(-5.5,-10.5) AD9(-4.5,-10.5) AD10(-3.5,-10.5) AD11(-2.5,-10.5) AD12(-1.5,-10.5) AD13(-0.5,-10.5) AD14(0.5,-10.5) AD15(1.5,-10.5) AD16(2.5,-10.5) AD17(3.5,-10.5) AD18(4.5,-10.5) AD19(5.5,-10.5) AD20(6.5,-10.5) AD21(7.5,-10.5) AD22(8.5,-10.5) AD23(9.5,-10.5) AD24(10.5,-10.5) AD25(11.5,-10.5) AD26(12.5,-10.5) AE1(-12.5,-11.5) AE2(-11.5,-11.5) AE3(-10.5,-11.5) AE4(-9.5,-11.5) AE5(-8.5,-11.5) AE6(-7.5,-11.5) AE7(-6.5,-11.5) AE8(-5.5,-11.5) AE9(-4.5,-11.5) AE10(-3.5,-11.5) AE11(-2.5,-11.5) AE12(-1.5,-11.5) AE13(-0.5,-11.5) AE14(0.5,-11.5) AE15(1.5,-11.5) AE16(2.5,-11.5) AE17(3.5,-11.5) AE18(4.5,-11.5) AE19(5.5,-11.5) AE20(6.5,-11.5) AE21(7.5,-11.5) AE22(8.5,-11.5) AE23(9.5,-11.5) AE24(10.5,-11.5) AE25(11.5,-11.5) AE26(12.5,-11.5) AF1(-12.5,-12.5) AF2(-11.5,-12.5) AF3(-10.5,-12.5) AF4(-9.5,-12.5) AF5(-8.5,-12.5) AF6(-7.5,-12.5) AF7(-6.5,-12.5) AF8(-5.5,-12.5) AF9(-4.5,-12.5) AF10(-3.5,-12.5) AF11(-2.5,-12.5) AF12(-1.5,-12.5) AF13(-0.5,-12.5) AF14(0.5,-12.5) AF15(1.5,-12.5) AF16(2.5,-12.5) AF17(3.5,-12.5) AF18(4.5,-12.5) AF19(5.5,-12.5) AF20(6.5,-12.5) AF21(7.5,-12.5) AF22(8.5,-12.5) AF23(9.5,-12.5) AF24(10.5,-12.5) AF25(11.5,-12.5) AF26(12.5,-12.5) B1(-12.5,11.5) B2(-11.5,11.5) B3(-10.5,11.5) B4(-9.5,11.5) B5(-8.5,11.5) B6(-7.5,11.5) B7(-6.5,11.5) B8(-5.5,11.5) B9(-4.5,11.5) B10(-3.5,11.5) B11(-2.5,11.5) B12(-1.5,11.5) B13(-0.5,11.5) B14(0.5,11.5) B15(1.5,11.5) B16(2.5,11.5) B17(3.5,11.5) B18(4.5,11.5) B19(5.5,11.5) B20(6.5,11.5) B21(7.5,11.5) B22(8.5,11.5) B23(9.5,11.5) B24(10.5,11.5) B25(11.5,11.5) B26(12.5,11.5) C1(-12.5,10.5) C2(-11.5,10.5) C3(-10.5,10.5) C4(-9.5,10.5) C5(-8.5,10.5) C6(-7.5,10.5) C7(-6.5,10.5) C8(-5.5,10.5) C9(-4.5,10.5) C10(-3.5,10.5) C11(-2.5,10.5) C12(-1.5,10.5) C13(-0.5,10.5) C14(0.5,10.5) C15(1.5,10.5) C16(2.5,10.5) C17(3.5,10.5) C18(4.5,10.5) C19(5.5,10.5) C20(6.5,10.5) C21(7.5,10.5) C22(8.5,10.5) C23(9.5,10.5) C24(10.5,10.5) C25(11.5,10.5) C26(12.5,10.5) D1(-12.5,9.5) D2(-11.5,9.5) D3(-10.5,9.5) D4(-9.5,9.5) D5(-8.5,9.5) D6(-7.5,9.5) D7(-6.5,9.5) D8(-5.5,9.5) D9(-4.5,9.5) D10(-3.5,9.5) D11(-2.5,9.5) D12(-1.5,9.5) D13(-0.5,9.5) D14(0.5,9.5) D15(1.5,9.5) D16(2.5,9.5) D17(3.5,9.5) D18(4.5,9.5) D19(5.5,9.5) D20(6.5,9.5) D21(7.5,9.5) D22(8.5,9.5) D23(9.5,9.5) D24(10.5,9.5) D25(11.5,9.5) D26(12.5,9.5) E1(-12.5,8.5) E2(-11.5,8.5) E3(-10.5,8.5) E4(-9.5,8.5) E5(-8.5,8.5) E6(-7.5,8.5) E7(-6.5,8.5) E8(-5.5,8.5) E9(-4.5,8.5) E10(-3.5,8.5) E11(-2.5,8.5) E12(-1.5,8.5) E13(-0.5,8.5) E14(0.5,8.5) E15(1.5,8.5) E16(2.5,8.5) E17(3.5,8.5) E18(4.5,8.5) E19(5.5,8.5) E20(6.5,8.5) E21(7.5,8.5) E22(8.5,8.5) E23(9.5,8.5) E24(10.5,8.5) E25(11.5,8.5) E26(12.5,8.5) F1(-12.5,7.5) F2(-11.5,7.5) F3(-10.5,7.5) F4(-9.5,7.5) F5(-8.5,7.5) F6(-7.5,7.5) F7(-6.5,7.5) F8(-5.5,7.5) F9(-4.5,7.5) F10(-3.5,7.5) F11(-2.5,7.5) F12(-1.5,7.5) F13(-0.5,7.5) F14(0.5,7.5) F15(1.5,7.5) F16(2.5,7.5) F17(3.5,7.5) F18(4.5,7.5) F19(5.5,7.5) F20(6.5,7.5) F21(7.5,7.5) F22(8.5,7.5) F23(9.5,7.5) F24(10.5,7.5) F25(11.5,7.5) F26(12.5,7.5) G1(-12.5,6.5) G2(-11.5,6.5) G3(-10.5,6.5) G4(-9.5,6.5) G5(-8.5,6.5) G6(-7.5,6.5) G7(-6.5,6.5) G8(-5.5,6.5) G9(-4.5,6.5) G10(-3.5,6.5) G11(-2.5,6.5) G12(-1.5,6.5) G13(-0.5,6.5) G14(0.5,6.5) G15(1.5,6.5) G16(2.5,6.5) G17(3.5,6.5) G18(4.5,6.5) G19(5.5,6.5) G20(6.5,6.5) G21(7.5,6.5) G22(8.5,6.5) G23(9.5,6.5) G24(10.5,6.5) G25(11.5,6.5) G26(12.5,6.5) H1(-12.5,5.5) H2(-11.5,5.5) H3(-10.5,5.5) H4(-9.5,5.5) H5(-8.5,5.5) H6(-7.5,5.5) H7(-6.5,5.5) H8(-5.5,5.5) H9(-4.5,5.5) H10(-3.5,5.5) H11(-2.5,5.5) H12(-1.5,5.5) H13(-0.5,5.5) H14(0.5,5.5) H15(1.5,5.5) H16(2.5,5.5) H17(3.5,5.5) H18(4.5,5.5) H19(5.5,5.5) H20(6.5,5.5) H21(7.5,5.5) H22(8.5,5.5) H23(9.5,5.5) H24(10.5,5.5) H25(11.5,5.5) H26(12.5,5.5) J1(-12.5,4.5) J2(-11.5,4.5) J3(-10.5,4.5) J4(-9.5,4.5) J5(-8.5,4.5) J6(-7.5,4.5) J7(-6.5,4.5) J8(-5.5,4.5) J9(-4.5,4.5) J10(-3.5,4.5) J11(-2.5,4.5) J12(-1.5,4.5) J13(-0.5,4.5) J14(0.5,4.5) J15(1.5,4.5) J16(2.5,4.5) J17(3.5,4.5) J18(4.5,4.5) J19(5.5,4.5) J20(6.5,4.5) J21(7.5,4.5) J22(8.5,4.5) J23(9.5,4.5) J24(10.5,4.5) J25(11.5,4.5) J26(12.5,4.5) K1(-12.5,3.5) K2(-11.5,3.5) K3(-10.5,3.5) K4(-9.5,3.5) K5(-8.5,3.5) K6(-7.5,3.5) K7(-6.5,3.5) K8(-5.5,3.5) K9(-4.5,3.5) K10(-3.5,3.5) K11(-2.5,3.5) K12(-1.5,3.5) K13(-0.5,3.5) K14(0.5,3.5) K15(1.5,3.5) K16(2.5,3.5) K17(3.5,3.5) K18(4.5,3.5) K19(5.5,3.5) K20(6.5,3.5) K21(7.5,3.5) K22(8.5,3.5) K23(9.5,3.5) K24(10.5,3.5) K25(11.5,3.5) K26(12.5,3.5) L1(-12.5,2.5) L2(-11.5,2.5) L3(-10.5,2.5) L4(-9.5,2.5) L5(-8.5,2.5) L6(-7.5,2.5) L7(-6.5,2.5) L8(-5.5,2.5) L9(-4.5,2.5) L10(-3.5,2.5) L11(-2.5,2.5) L12(-1.5,2.5) L13(-0.5,2.5) L14(0.5,2.5) L15(1.5,2.5) L16(2.5,2.5) L17(3.5,2.5) L18(4.5,2.5) L19(5.5,2.5) L20(6.5,2.5) L21(7.5,2.5) L22(8.5,2.5) L23(9.5,2.5) L24(10.5,2.5) L25(11.5,2.5) L26(12.5,2.5) M1(-12.5,1.5) M2(-11.5,1.5) M3(-10.5,1.5) M4(-9.5,1.5) M5(-8.5,1.5) M6(-7.5,1.5) M7(-6.5,1.5) M8(-5.5,1.5) M9(-4.5,1.5) M10(-3.5,1.5) M11(-2.5,1.5) M12(-1.5,1.5) M13(-0.5,1.5) M14(0.5,1.5) M15(1.5,1.5) M16(2.5,1.5) M17(3.5,1.5) M18(4.5,1.5) M19(5.5,1.5) M20(6.5,1.5) M21(7.5,1.5) M22(8.5,1.5) M23(9.5,1.5) M24(10.5,1.5) M25(11.5,1.5) M26(12.5,1.5) N1(-12.5,0.5) N2(-11.5,0.5) N3(-10.5,0.5) N4(-9.5,0.5) N5(-8.5,0.5) N6(-7.5,0.5) N7(-6.5,0.5) N8(-5.5,0.5) N9(-4.5,0.5) N10(-3.5,0.5) N11(-2.5,0.5) N12(-1.5,0.5) N13(-0.5,0.5) N14(0.5,0.5) N15(1.5,0.5) N16(2.5,0.5) N17(3.5,0.5) N18(4.5,0.5) N19(5.5,0.5) N20(6.5,0.5) N21(7.5,0.5) N22(8.5,0.5) N23(9.5,0.5) N24(10.5,0.5) N25(11.5,0.5) N26(12.5,0.5) P1(-12.5,-0.5) P2(-11.5,-0.5) P3(-10.5,-0.5) P4(-9.5,-0.5) P5(-8.5,-0.5) P6(-7.5,-0.5) P7(-6.5,-0.5) P8(-5.5,-0.5) P9(-4.5,-0.5) P10(-3.5,-0.5) P11(-2.5,-0.5) P12(-1.5,-0.5) P13(-0.5,-0.5) P14(0.5,-0.5) P15(1.5,-0.5) P16(2.5,-0.5) P17(3.5,-0.5) P18(4.5,-0.5) P19(5.5,-0.5) P20(6.5,-0.5) P21(7.5,-0.5) P22(8.5,-0.5) P23(9.5,-0.5) P24(10.5,-0.5) P25(11.5,-0.5) P26(12.5,-0.5) R1(-12.5,-1.5) R2(-11.5,-1.5) R3(-10.5,-1.5) R4(-9.5,-1.5) R5(-8.5,-1.5) R6(-7.5,-1.5) R7(-6.5,-1.5) R8(-5.5,-1.5) R9(-4.5,-1.5) R10(-3.5,-1.5) R11(-2.5,-1.5) R12(-1.5,-1.5) R13(-0.5,-1.5) R14(0.5,-1.5) R15(1.5,-1.5) R16(2.5,-1.5) R17(3.5,-1.5) R18(4.5,-1.5) R19(5.5,-1.5) R20(6.5,-1.5) R21(7.5,-1.5) R22(8.5,-1.5) R23(9.5,-1.5) R24(10.5,-1.5) R25(11.5,-1.5) R26(12.5,-1.5) T1(-12.5,-2.5) T2(-11.5,-2.5) T3(-10.5,-2.5) T4(-9.5,-2.5) T5(-8.5,-2.5) T6(-7.5,-2.5) T7(-6.5,-2.5) T8(-5.5,-2.5) T9(-4.5,-2.5) T10(-3.5,-2.5) T11(-2.5,-2.5) T12(-1.5,-2.5) T13(-0.5,-2.5) T14(0.5,-2.5) T15(1.5,-2.5) T16(2.5,-2.5) T17(3.5,-2.5) T18(4.5,-2.5) T19(5.5,-2.5) T20(6.5,-2.5) T21(7.5,-2.5) T22(8.5,-2.5) T23(9.5,-2.5) T24(10.5,-2.5) T25(11.5,-2.5) T26(12.5,-2.5) U1(-12.5,-3.5) U2(-11.5,-3.5) U3(-10.5,-3.5) U4(-9.5,-3.5) U5(-8.5,-3.5) U6(-7.5,-3.5) U7(-6.5,-3.5) U8(-5.5,-3.5) U9(-4.5,-3.5) U10(-3.5,-3.5) U11(-2.5,-3.5) U12(-1.5,-3.5) U13(-0.5,-3.5) U14(0.5,-3.5) U15(1.5,-3.5) U16(2.5,-3.5) U17(3.5,-3.5) U18(4.5,-3.5) U19(5.5,-3.5) U20(6.5,-3.5) U21(7.5,-3.5) U22(8.5,-3.5) U23(9.5,-3.5) U24(10.5,-3.5) U25(11.5,-3.5) U26(12.5,-3.5) V1(-12.5,-4.5) V2(-11.5,-4.5) V3(-10.5,-4.5) V4(-9.5,-4.5) V5(-8.5,-4.5) V6(-7.5,-4.5) V7(-6.5,-4.5) V8(-5.5,-4.5) V9(-4.5,-4.5) V10(-3.5,-4.5) V11(-2.5,-4.5) V12(-1.5,-4.5) V13(-0.5,-4.5) V14(0.5,-4.5) V15(1.5,-4.5) V16(2.5,-4.5) V17(3.5,-4.5) V18(4.5,-4.5) V19(5.5,-4.5) V20(6.5,-4.5) V21(7.5,-4.5) V22(8.5,-4.5) V23(9.5,-4.5) V24(10.5,-4.5) V25(11.5,-4.5) V26(12.5,-4.5) W1(-12.5,-5.5) W2(-11.5,-5.5) W3(-10.5,-5.5) W4(-9.5,-5.5) W5(-8.5,-5.5) W6(-7.5,-5.5) W7(-6.5,-5.5) W8(-5.5,-5.5) W9(-4.5,-5.5) W10(-3.5,-5.5) W11(-2.5,-5.5) W12(-1.5,-5.5) W13(-0.5,-5.5) W14(0.5,-5.5) W15(1.5,-5.5) W16(2.5,-5.5) W17(3.5,-5.5) W18(4.5,-5.5) W19(5.5,-5.5) W20(6.5,-5.5) W21(7.5,-5.5) W22(8.5,-5.5) W23(9.5,-5.5) W24(10.5,-5.5) W25(11.5,-5.5) W26(12.5,-5.5) Y1(-12.5,-6.5) Y2(-11.5,-6.5) Y3(-10.5,-6.5) Y4(-9.5,-6.5) Y5(-8.5,-6.5) Y6(-7.5,-6.5) Y7(-6.5,-6.5) Y8(-5.5,-6.5) Y9(-4.5,-6.5) Y10(-3.5,-6.5) Y11(-2.5,-6.5) Y12(-1.5,-6.5) Y13(-0.5,-6.5) Y14(0.5,-6.5) Y15(1.5,-6.5) Y16(2.5,-6.5) Y17(3.5,-6.5) Y18(4.5,-6.5) Y19(5.5,-6.5) Y20(6.5,-6.5) Y21(7.5,-6.5) Y22(8.5,-6.5) Y23(9.5,-6.5) Y24(10.5,-6.5) Y25(11.5,-6.5) Y26(12.5,-6.5)
  round 1 on Mech7 paste-0.55 mask+1: FID1(-15,15) FID1(15,-15)
  round 1 smd paste-0.55 mask+0.762: FID1(-15,15) FID1(15,-15)
  Top Layer keep-out circle w0.2: c15,-15 r1
  Top Layer keep-out circle w0.2: c-15,15 r1
  silkscreen extent -14.77,-13.5 13.5,13.5, body extent -13.55,-13.45 13.45,13.55, height 2.6
CAPC1005-STAR#1 [mm] "Chip Capacitor 1005"
  rect 0.6x0.6 smd: 1(-0.525,0) 2(0.525,0)
  silkscreen extent -0.05,-0.38 0.05,0.38, body extent -0.57,-0.3 0.57,0.3, height 0.2
CAPC1005-STAR#2 [mm] "Chip Capacitor 1005"
  rect 0.6x0.6 smd mask+0.025: 1(-0.525,0)
  rect 0.6x0.6 smd: 2(0.525,0)
  silkscreen extent -0.05,-0.38 0.05,0.38, body extent -0.57,-0.3 0.57,0.3, height 0.2
CAPC1608-STAR [mm] "Capacitor SMD 0603 (1608)"
  rect 0.9x0.8 smd: 1(-0.8,0) 2(0.8,0)
  silkscreen extent 0,-0.4 0,0.4, body extent -1.07,-0.3 1.12,0.3, height 0.8
CAPC2012-STAR [mm] "0805 Capacitor SMD - Startronics"
  rect 1x1.25 smd: 1(-1,0) 2(1,0)
  silkscreen extent -0.4,-1 0.4,1, body extent -1.32,-0.69 1.23,0.67, height 0.5
CAPC3216-STAR [mm] "Capacitor 1206 (3216) for Startronics"
  rect 1x1.6 smd: 1(-1.45,0) 2(1.45,0)
  silkscreen extent -0.62,-1.1 0.62,1.1, body extent -1.64,-0.89 1.63,0.86, height 0.9
CAPC3225-STAR [mm] "1210 Capacitor SMD - Startronics"
  rect 1x2.75 smd: 1(-1.5,0) 2(1.5,0)
  silkscreen extent -0.7,-1.5 0.7,1.5, body extent -1.94,-1.2 1.89,1.29, height 1.5
CAPC7343-STAR [mm] "Capcacitor SMD 7.3 x 4.3mm (D-Case)"
  rect 2.6x2.4 smd: 1(-3.202,0.007) 2(3.198,0.007)
  silkscreen extent -5.32,-2.39 5.08,2.41, body extent -3.5,-2.03 3.51,2.04, height 1.75
IND-EPCOS-SMD-B82559 [mm]
  rect 4.4x10.4 smd: 1(0,0) 2(8.4,0)
  silkscreen extent -2.5,-5.5 11,5.5
LEAD_FREE_S [mil]
  silkscreen extent -125,-125 125,125
LED2012-STAR [mm] "0805 LED SMD - Startronics"
  rect 1x1.25 smd: 1(1,0) 2(-1,0)
  silkscreen extent -2.27,-1 1.8,1, body extent -1.6,-0.6 1.5,0.6, height 0.67
Logo-Altium [mil]
  silkscreen extent -1025,-99 -556,102
MOUNTING_HOLE_3MM [mm] "Non-plated mounting hole for 3mm screw"
  round 3.8 hole 3.4 mask+0.2: MOUNT(0,0)
  Top Layer circle w1: c0,0 r2.3
  Top Layer region: -2.8,-2.8 2.8,-2.8 2.8,2.8 -2.8,2.8
  Top Layer keep-out region: -3.3,-3.3 3.3,-3.3 3.3,3.3 -3.3,3.3
  Bottom Layer region: -2.8,-2.8 2.8,-2.8 2.8,2.8 -2.8,2.8
  Bottom Layer keep-out region: -3.3,-3.3 3.3,-3.3 3.3,3.3 -3.3,3.3
  Keep-Out Layer circle w1.2: c0,0 r2.5
NETTIE-SMT2-8X8 [mm]
  rect 0.4x0.2 smd paste-0.11 mask-0.11: 1(-0.891,-0.006) 2(-0.691,-0.006)
RESC1005-STAR [mm] "Chip Inductor 1005"
  rect 0.575x0.6 smd: 1(-0.538,0) 2(0.538,0)
  silkscreen extent -0.05,-0.38 0.05,0.38, body extent -0.71,-0.25 0.72,0.26, height 0.25
RESNET-1005X4 [mm] "Resistor network 4 x 1005 (0402)"
  rect 0.3x0.83 smd: 1(-0.75,-0.64) 2(-0.25,-0.64) 3(0.25,-0.64) 4(0.75,-0.64) 5(0.75,0.64) 6(0.25,0.64) 7(-0.25,0.64) 8(-0.75,0.64)
  silkscreen extent -1.15,-1 1.15,1, body extent -0.92,-0.84 1.04,0.81, height 0.4
SOP63P602-16 [mil]
  rect 82x16 smd: 1(-116,87.5) 2(-116,62) 3(-116,37.5) 4(-116,12.5) 5(-116,-12.5) 6(-116,-37.5) 7(-116,-62.5) 8(-116,-87.5) 9(116,-87.5) 10(116,-62.5) 11(116,-37.5) 12(116,-12.5) 13(116,12.5) 14(116,37.5) 15(116,62.5) 16(116,87.5)
  silkscreen extent -100,-100 60,125, body extent -107,-100 108,103, height 29
SOP65P490-8 [mm]
  rect 1.5x0.35 smd: 1(-2.275,0.975) 2(-2.3,0.325) 3(-2.3,-0.325) 4(-2.3,-0.975) 5(2.275,-0.975) 6(2.275,-0.325) 7(2.3,0.325) 8(2.3,0.975)
  silkscreen extent -2.38,-1.3 1.3,1.75, body extent -2.39,-1.23 2.41,1.28, height 1
SOT95P280-5 [mm] "SOT-23/SC-74A; 5 Leads; Body 3.1 x 3 mm, inc. leads (LxW max)"
  rect 0.6x1.3 smd: 1(-0.95,-1.4) 2(0,-1.4) 3(0.95,-1.4) 4(0.95,1.4)
  rect 0.6x1.25 smd: 5(-0.95,1.4)
  silkscreen extent -1.55,-0.9 1.55,0.9, body extent -1.51,-1.49 1.52,1.52, height 0.8
TestPin [mil]
  round 60 hole 35.43: 1(0,0)
  silkscreen extent -41,-39 156,39
TSOC6 [mil]
  rect 25x71 smd: 1(-50,-75) 2(0,-75) 3(50,-75) 4(50,75) 5(0,75) 6(-50,75)
  silkscreen extent -115,-80 85,80, body extent -79,-90 84,91, height 40
TSOP80P1176-44 [mm]
  rect 0.5x1.4 smd: 1(-8.4,-5.7) 2(-7.6,-5.7) 3(-6.8,-5.7) 4(-6,-5.7) 5(-5.2,-5.7) 6(-4.4,-5.7) 7(-3.6,-5.7) 8(-2.8,-5.7) 9(-2,-5.7) 10(-1.2,-5.7) 11(-0.4,-5.7) 12(0.4,-5.7) 13(1.2,-5.7) 14(2,-5.7) 15(2.8,-5.7) 16(3.6,-5.7) 17(4.4,-5.7) 18(5.2,-5.7) 19(6,-5.7) 20(6.8,-5.7) 21(7.6,-5.7) 22(8.4,-5.7) 23(8.4,5.7) 24(7.6,5.7) 25(6.8,5.7) 26(6,5.7) 27(5.2,5.7) 28(4.4,5.7) 29(3.6,5.7) 30(2.8,5.7) 31(2,5.7) 32(1.2,5.7) 33(0.4,5.7) 34(-0.4,5.7) 35(-1.2,5.7) 36(-2,5.7) 37(-2.8,5.7) 38(-3.6,5.7) 39(-4.4,5.7) 40(-5.2,5.7) 41(-6,5.7) 42(-6.8,5.7) 43(-7.6,5.7) 44(-8.4,5.7)
  silkscreen extent -9.29,-5.7 9.26,4.45, body extent -9.24,-5.95 9.26,5.84, height 1
TSOP80P1176-54 [mm] "Plastic Small Outline; 54 Leads; Body Width 10.16 mm"
  rect 0.5x1.4 smd: 1(-10.4,-5.7) 2(-9.6,-5.7) 3(-8.8,-5.7) 4(-8,-5.7) 5(-7.2,-5.7) 6(-6.4,-5.7) 7(-5.6,-5.7) 8(-4.8,-5.7) 9(-4,-5.7) 10(-3.2,-5.7) 11(-2.4,-5.7) 12(-1.6,-5.7) 13(-0.8,-5.7) 14(0,-5.7) 15(0.8,-5.7) 16(1.6,-5.7) 17(2.4,-5.7) 18(3.2,-5.7) 19(4,-5.7) 20(4.8,-5.7) 21(5.6,-5.7) 22(6.4,-5.7) 23(7.2,-5.7) 24(8,-5.7) 25(8.8,-5.7) 26(9.6,-5.7) 27(10.4,-5.7) 28(10.4,5.7) 29(9.6,5.7) 30(8.8,5.7) 31(8,5.7) 32(7.2,5.7) 33(6.4,5.7) 34(5.6,5.7) 35(4.8,5.7) 36(4,5.7) 37(3.2,5.7) 38(2.4,5.7) 39(1.6,5.7) 40(0.8,5.7) 41(0,5.7) 42(-0.8,5.7) 43(-1.6,5.7) 44(-2.4,5.7) 45(-3.2,5.7) 46(-4,5.7) 47(-4.8,5.7) 48(-5.6,5.7) 49(-6.4,5.7) 50(-7.2,5.7) 51(-8,5.7) 52(-8.8,5.7) 53(-9.6,5.7) 54(-10.4,5.7)
  silkscreen extent -11.33,-5.67 11.15,4.4, body extent -11.23,-5.96 11.19,5.97, height 1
